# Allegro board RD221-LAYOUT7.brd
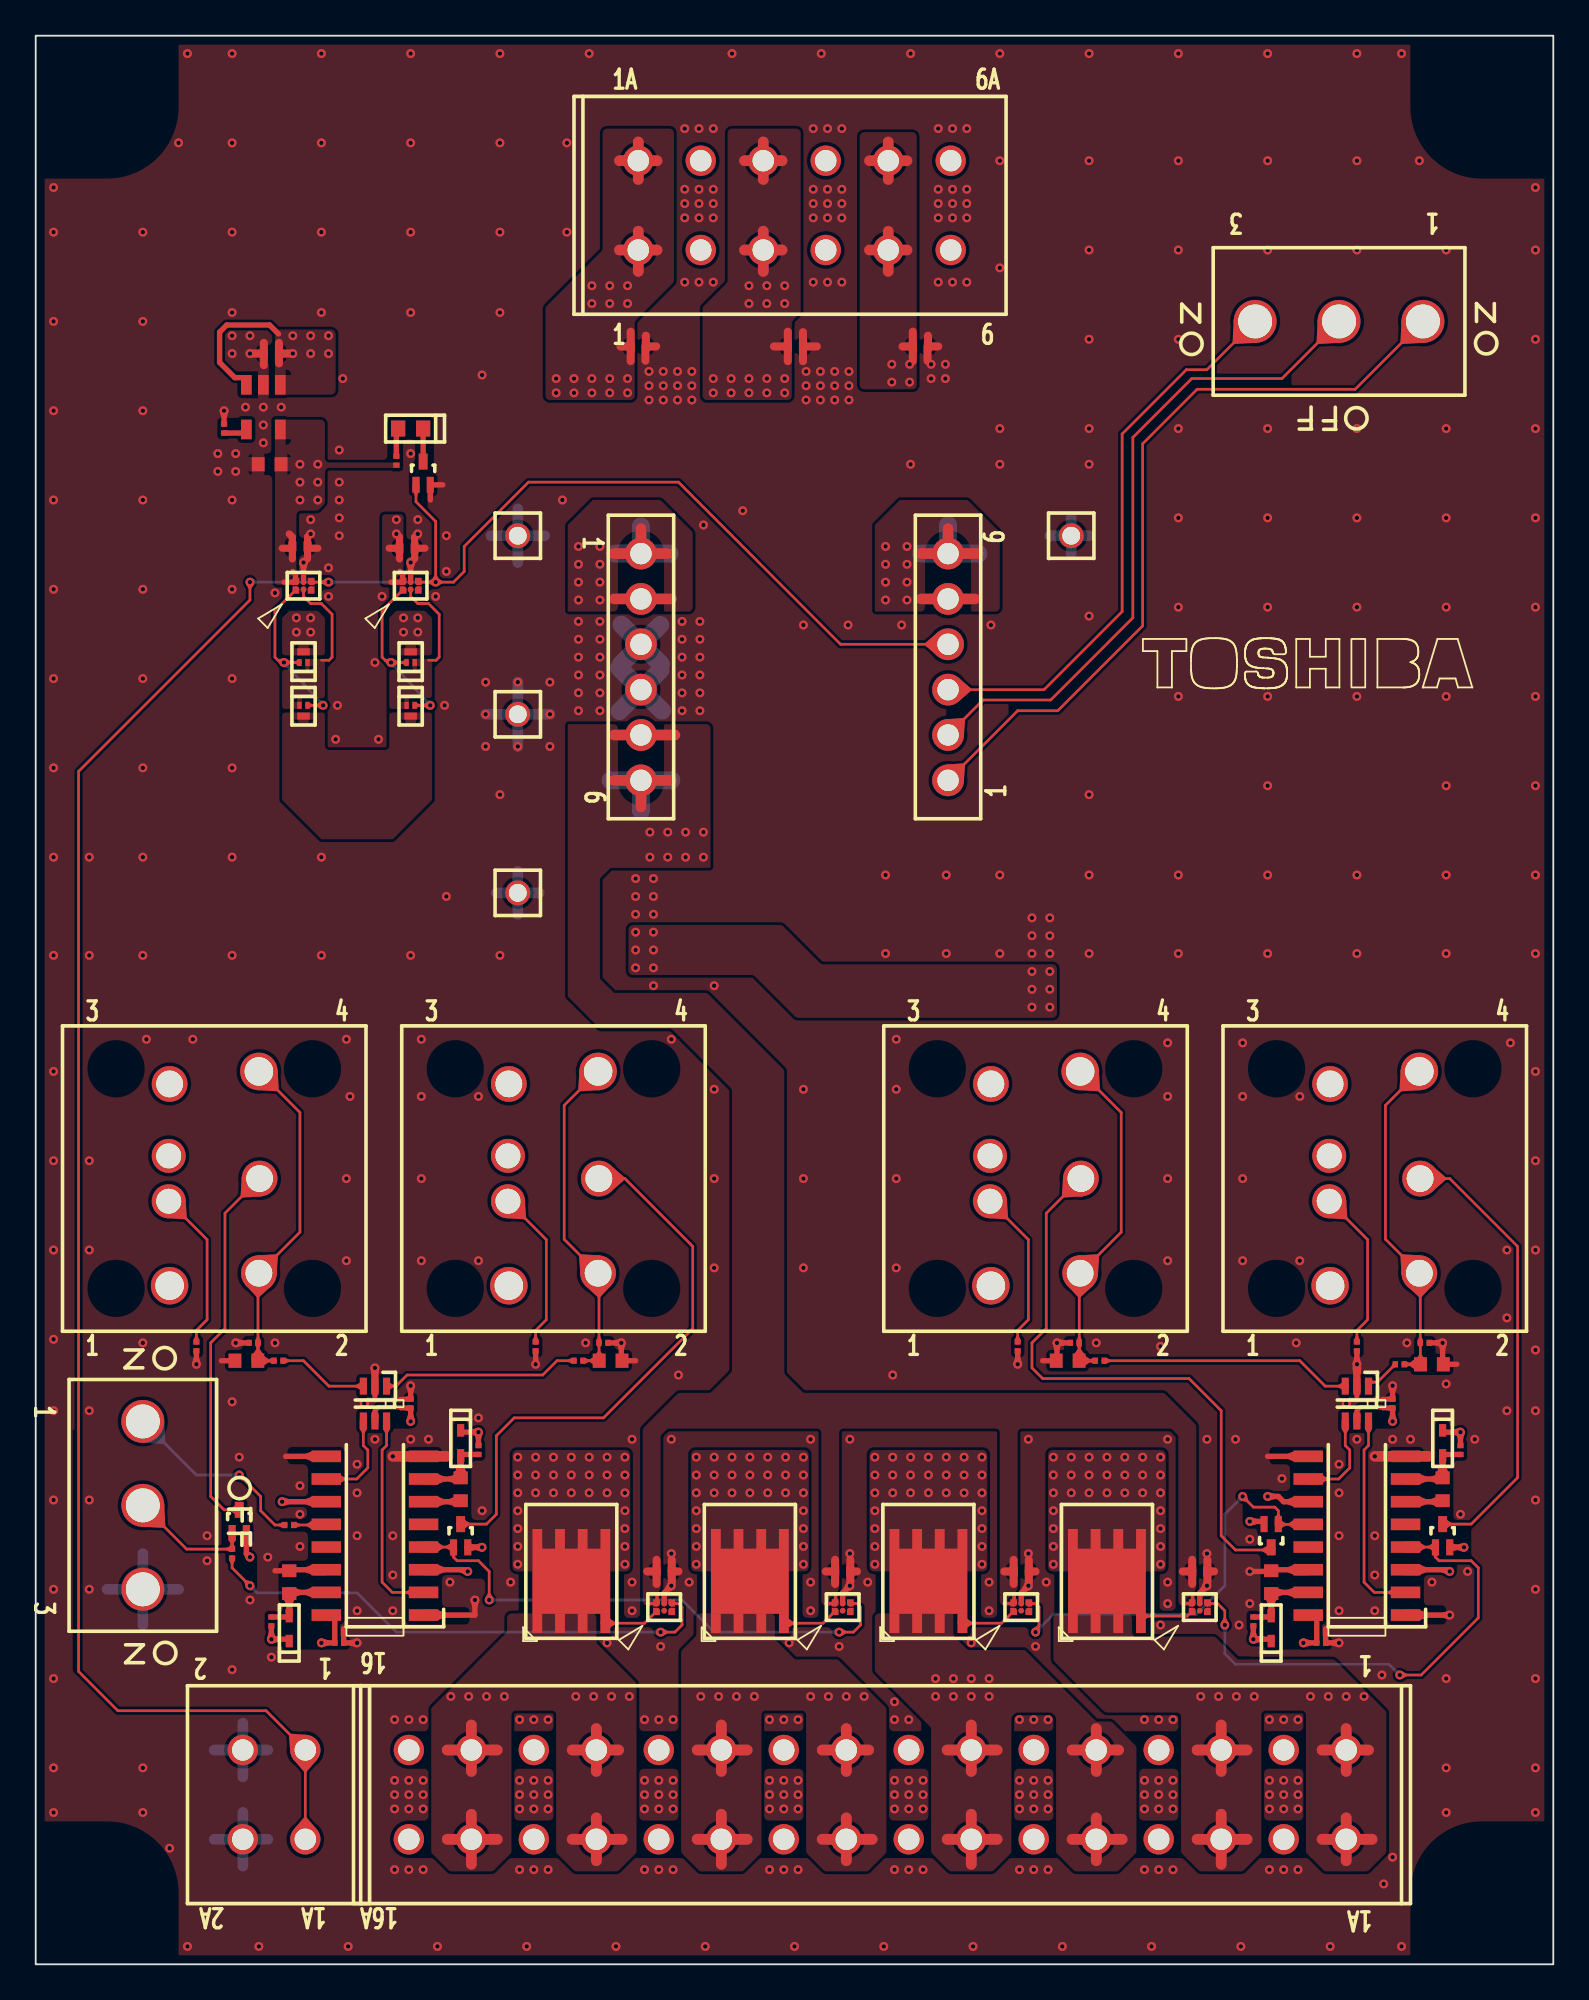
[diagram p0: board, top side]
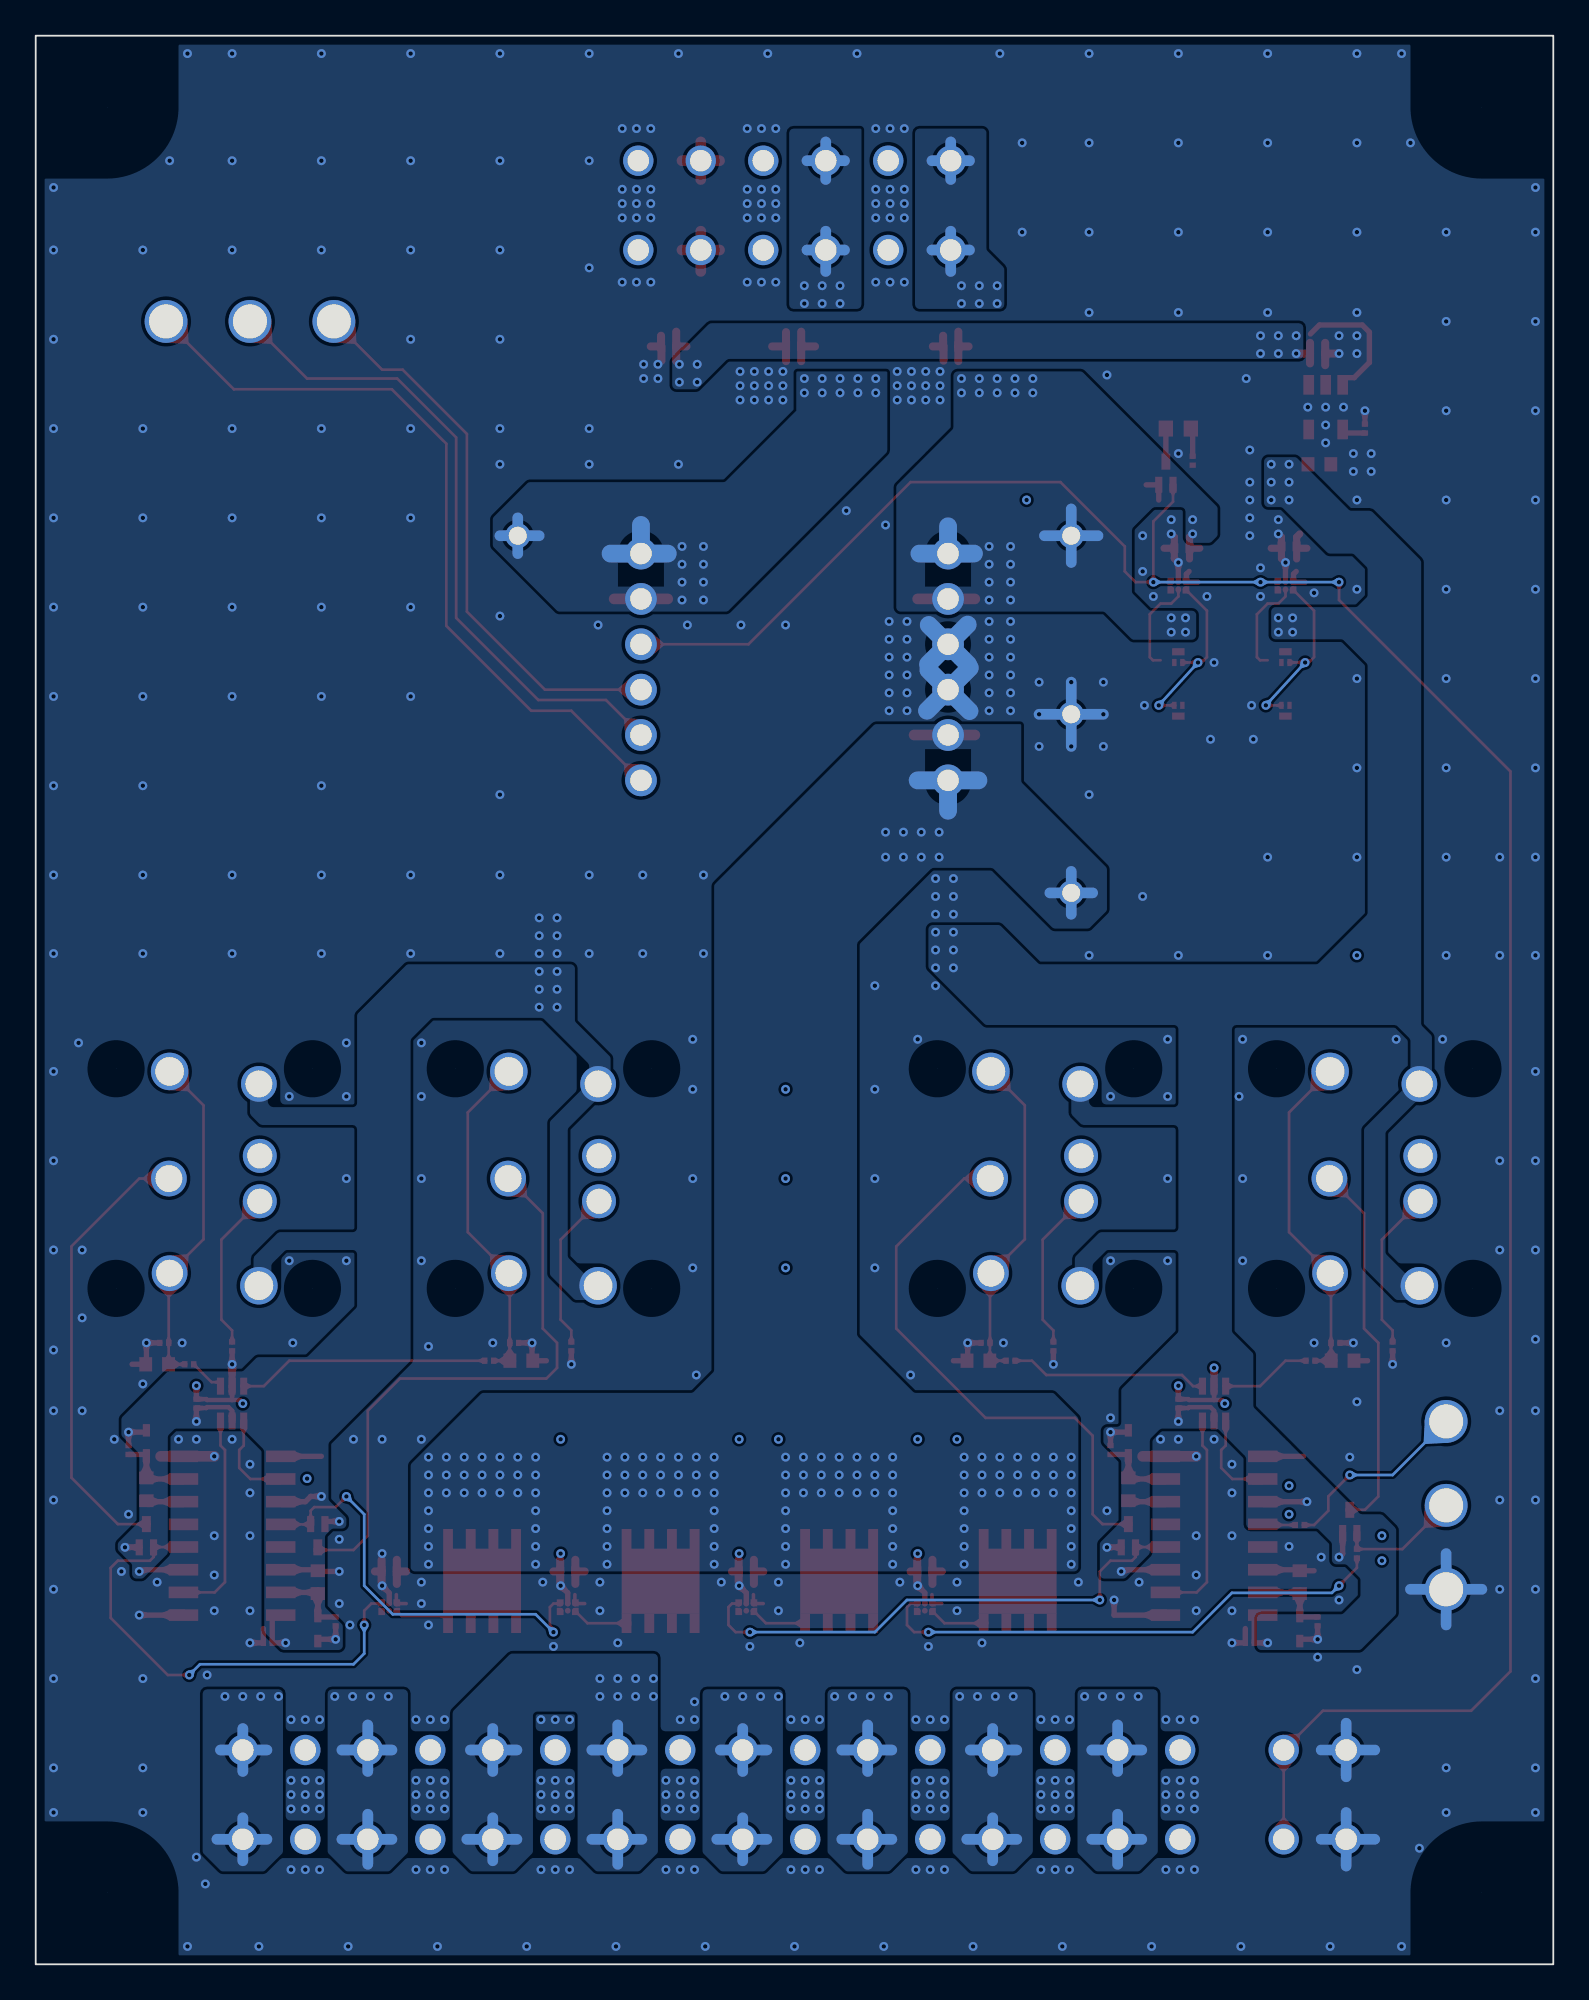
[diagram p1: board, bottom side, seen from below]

Outline 85 x 108 mm; copper layers: TOP, CONDUCTIVE2, CONDUCTIVE3, BOTTOM. Coordinates in mm from the lower left corner of the outline.
Outline path: rectangle 0,0 85,108

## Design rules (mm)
constraint set DEFAULT: 

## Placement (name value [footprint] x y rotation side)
C1  -  [KC00051KD]  20.8 79.3 0 top
C2  -  [KC00051KD]  14.8 79.4 0 top
C3  -  [KC00051KD]  65.2 22 0 top
C4  -  [KC00051KD]  55.2 22 0 top
C5  -  [KC00081KD]  78.2 33.6 0 top
C6  -  [KC00081KD]  57.8 33.8 180 top
C7  -  [KC00081KD]  78.8 26.6 90 top
C8  -  [KC00081KD]  69.2 21.4 270 top
C9  -  [KC00051KD]  45.2 22 0 top
C10  -  [KC00081KD]  32.2 33.8 0 top
C11  -  [KC00081KD]  11.8 33.8 180 top
C12  -  [KC00051KD]  35.2 22 0 top
C13  -  [KC00540KD]  72 18 180 top
C14  -  [KC00540KD]  17 18 180 top
C15  -  [KC00081KD]  14.2 21.4 270 top
C16  -  [KC00081KD]  23.8 26.6 270 top
C17  -  [KC00051KD]  13.2 90.2 180 top
C18  -  [KC00081KD]  13.1 84 180 top
C19  -  [KC00540KD]  10.55 86 270 top
C20  -  [KC00540KD]  76 31.4 270 top
C21  -  [KC00540KD]  21 31.4 270 top
C22  -  [KC00051KD]  49.55 90.6 0 top
C23  -  [KC00051KD]  42.55 90.6 0 top
C24  -  [KC00051KD]  33.75 90.6 0 top
CN1  -  [CU12010TD]  33.75 96 0 top
CN2  -  [CU12030TD]  73.4 12 180 top
CN3  -  [CU12020TD]  15.1 12 180 top
CN4  -  [CU11170TD]  51.1 66.3 90 top
CN5  -  [CU11170TD]  33.9 79 270 top
D1  -  [D8101D1KD]  78.8 29.2 90 top
D2  -  [D8101D1KD]  69.2 18.8 270 top
D3  -  [D8101D1KD]  23.8 29.2 90 top
D4  -  [D8101D1KD]  14.2 18.8 270 top
IC1  -  [MM00631KD]  12.75 87.2 180 top
IC2  -  [BA10620KD]  21 77.2 0 top
IC3  -  [BA10620KD]  15 77.2 0 top
IC4  -  [BA10620KD]  65.2 20 0 top
IC5  -  [SP10580KD]  74 24 90 top
IC6  -  [BA10620KD]  55.2 20 0 top
IC7  -  [BA10620KD]  45.2 20 0 top
IC8  -  [SP10580KD]  19 24 90 top
IC9  -  [BA10620KD]  35.2 20 0 top
IC10  -  [MM00451KD]  74 31.4 180 top
IC11  -  [MM00451KD]  19 31.4 180 top
LED1  -  [KC01110KD]  21 86 0 top
NOREF  -  [unnamed]  4 104 180 top
NOREF#2  -  [unnamed]  4 4 180 top
NOREF#3  -  [unnamed]  81 4 180 top
NOREF#4  -  [unnamed]  81 104 180 top
NOREF#5  -  [#2]  59.3 68.79 0 top
Q1  -  [LA10710KD]  21 73.2 90 top
Q2  -  [LA10710KD]  21 70.2 270 top
Q3  -  [LA10710KD]  15 73.2 90 top
Q4  -  [LA10710KD]  15 70.2 270 top
Q5  -  [MM11010KD]  21.7 83.5 0 top
Q6  -  [MM11010KD]  78.8 24 0 top
Q7  -  [SN10261KD]  60 22 0 top
Q8  -  [MM11010KD]  69.2 24 180 top
Q9  -  [SN10261KD]  50 22 0 top
Q10  -  [MM11010KD]  23.8 24 0 top
Q11  -  [SN10261KD]  40 22 0 top
Q12  -  [MM11010KD]  11.4 24.8 0 top
Q13  -  [SN10261KD]  30 22 0 top
R1  -  [KC00540KD]  74 34.6 270 top
R2  -  [KC00540KD]  55 34.6 270 top
R3  -  [KC00540KD]  58.2 34.8 180 top
R4  -  [KC00540KD]  77.8 34.8 0 top
R5  -  [KC00540KD]  20.2 84.2 270 top
R6  -  [KC00540KD]  79.8 28.8 270 top
R7  -  [KC00540KD]  68.2 19.2 90 top
R8  -  [KC00540KD]  28 34.6 270 top
R9  -  [KC00540KD]  31.8 34.8 0 top
R10  -  [KC00540KD]  12.2 34.8 180 top
R11  -  [KC00540KD]  24.8 28.8 270 top
R12  -  [KC00540KD]  13.2 19.2 90 top
R13  -  [KC00540KD]  9 34.6 270 top
R14  -  [KC00540KD]  76.4 33.6 0 top
R16  -  [KC00540KD]  30.4 33.8 0 top
R17  -  [KC00540KD]  13.6 33.8 0 top
R18  -  [KC00540KD]  14.2 24.6 0 top
R19  -  [KC00540KD]  11 23 270 top
R20  -  [KC00540KD]  59.6 33.8 0 top
SW1  -  [OD11430TD]  75 44 0 top
SW2  -  [OD11430TD]  56 44 0 top
SW3  -  [OD11430TD]  29 44 0 top
SW4  -  [OD11430TD]  10 44 0 top
SW5  -  [OD11420TD]  6 30.4 270 top
SW6  -  [OD11420TD]  77.7 92 180 top
TP1  -  [DP002X0KD]  27 80 0 top
TP2  -  [DP002X0KD]  58 80 0 top
TP3  -  [DP002X0KD]  27 60 0 top
TP4  -  [DP002X0KD]  27 70 0 top

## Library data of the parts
C1-C4 C9 C12 C17 C22-C24 = DP0000016125
C5 C6 C10 C11 = DP0000149011
C7 C8 C15 C16 = DP0000017116
C13 C14 C20 C21 = DP0000015406
C18 = DP0008993000
C19 = DP0000015127
CN1 = DP0010576000
CN2 = DP0010577000
CN3 = DP0010578000
CN4 CN5 = DP0010574000
D1-D4 = DP0005002000
IC1 = DP0010569000
IC2 = DP0010565000
IC3 IC4 IC6 IC7 IC9 = DP0010566000
IC5 IC8 = DP0010568000
IC10 IC11 = DP0010608000
LED1 = DP0010573000
Q1-Q4 = DP0010564000
Q5 = DP0010015000
Q6 Q8 Q10 Q12 = DP0010570000
Q7 Q9 Q11 Q13 = DP0010567000
R1 R2 R5 R8 R13 = DP0000152048
R3 R4 R9 R10 = DP0000152088
R6 R11 = DP0000152104
R7 R12 = DP0000155128
R14 R16-R20 = DP0000155000
SW1-SW4 = DP0010571000
SW5 SW6 = DP0010575000
TP1-TP4 = DP9000817000

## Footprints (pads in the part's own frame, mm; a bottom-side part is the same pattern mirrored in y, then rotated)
BA10620KD
  round 0.325 smd: A1(-0.4,-0.2) A2(-0.4,0.2) B1(0,-0.2) B2(0,0.2) C1(0.4,-0.2) C2(0.4,0.2)
CU11170TD
  round 1.778 hole 1.2: 1(0,0) 2(2.54,0) 3(5.08,0) 4(7.62,0) 5(10.16,0) 6(12.7,0)
CU12010TD
  round 1.7 hole 1.2: 1(0,0) 1A(0,5) 2(3.5,0) 2A(3.5,5) 3(7,0) 3A(7,5) 4(10.5,0) 4A(10.5,5) 5(14,0) 5A(14,5) 6(17.5,0) 6A(17.5,5)
CU12020TD
  round 1.7 hole 1.2: 1(0,0) 1A(0,5) 2(3.5,0) 2A(3.5,5)
CU12030TD
  round 1.7 hole 1.2: 1(0,0) 1A(0,5) 2(3.5,0) 2A(3.5,5) 3(7,0) 3A(7,5) 4(10.5,0) 4A(10.5,5) 5(14,0) 5A(14,5) 6(17.5,0) 6A(17.5,5) 7(21,0) 7A(21,5) 8(24.5,0) 8A(24.5,5) 9(28,0) 9A(28,5) 10(31.5,0) 10A(31.5,5) 11(35,0) 11A(35,5) 12(38.5,0) 12A(38.5,5) 13(42,0) 13A(42,5) 14(45.5,0) 14A(45.5,5) 15(49,0) 15A(49,5) 16(52.5,0) 16A(52.5,5)
D8101D1KD
  rect 0.7x0.4 smd: A(-0.7,0) C(0.7,0)
DP002X0KD
  round 1.397 hole 1: 1(0,0)
KC00051KD
  rect 0.45x0.55 smd: 1(-0.425,0) 2(0.425,0)
KC00081KD
  rect 0.72x0.8 smd: 1(-0.64,0) 2(0.64,0)
KC00540KD
  rect 0.3x0.35 smd: 1(-0.25,0) 2(0.25,0)
KC01110KD
  rect 0.8x0.9 smd: A(-0.7,0) C(0.7,0)
LA10710KD
  rect 0.4x0.7 smd: D(0.3,0)
  rect 0.4x0.25 smd: G(-0.3,0.225) S(-0.3,-0.225)
MM00451KD
  rect 0.4x0.95 smd: 1(-0.65,-0.975) 2(0,-0.975) 3(0.65,-0.975) 4(0.65,0.975) 5(0,0.975) 6(-0.65,0.975)
MM00631KD
  rect 0.6x1.1 smd: 1(-0.95,-1.25) 2(0,-1.25) 3(0.95,-1.25) 4(0.95,1.25) 5(-0.95,1.25)
MM11010KD
  rect 0.4x0.9 smd: B(-0.4,-0.65) E(0.4,-0.65)
  rect 0.5x0.9 smd: C(0,0.65)
OD11420TD
  round 2.4 hole 1.9: 1(0,0) 2(4.7,0) 3(9.4,0)
OD11430TD
  round 0.01 hole 2.2 unplated: (-5.5,6.15) (-5.5,-6.15) (5.5,6.15) (5.5,-6.15)
  round 2.1 hole 1.6: 1(-2.5,-6) 4(2.5,6)
  round 2 hole 1.5: 2(2.5,-5.3) 3(-2.5,5.3) LC(2.54,0)
  round 1.9 hole 1.4: L1(-2.55,1.27) L2(-2.55,-1.27)
SN10261KD
  rect 0.55x1.1 smd: 1(-1.905,-2.9) 2(-0.635,-2.9) 3(0.635,-2.9) 4(1.905,-2.9)
  custom 1.09x1.09 smd: 5(0,0)
SP10580KD
  rect 0.65x1.65 smd: 1(-4.445,-2.725) 2(-3.175,-2.725) 3(-1.905,-2.725) 4(-0.635,-2.725) 5(0.635,-2.725) 6(1.905,-2.725) 7(3.175,-2.725) 8(4.445,-2.725) 9(4.445,2.725) 10(3.175,2.725) 11(1.905,2.725) 12(0.635,2.725) 13(-0.635,2.725) 14(-1.905,2.725) 15(-3.175,2.725) 16(-4.445,2.725)
unnamed
  round 0.01 hole 3.5 unplated: (0,0)

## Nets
GND: C1.2 C2.2 C3.2 C4.2 C5.2 C6.2 C8.1 C9.2 C10.2 C11.2 C12.2 C13.1 C14.1 C15.1 C17.2 C18.2 C19.1 C20.1 C21.1 C22.2 C23.2 C24.2 CN1.2 CN1.2A CN1.4 CN1.4A CN1.6 CN1.6A CN2.2 CN2.2A CN2.4 CN2.4A CN2.6 CN2.6A CN2.8 CN2.8A CN2.10 CN2.10A CN2.12 CN2.12A CN2.14 CN2.14A CN2.16 CN2.16A CN3.2 CN3.2A CN5.3 CN5.4 IC1.2 IC2.B2 IC3.B2 IC4.B2 IC5.1 IC5.8 IC5.9 IC5.14 IC6.B2 IC7.B2 IC8.1 IC8.8 IC8.9 IC8.14 IC9.B2 IC10.2 IC11.2 Q5.E R1.2 R2.2 R3.2 R4.2 R8.2 R9.2 R10.2 R13.2 SW5.3 TP4.1
VDD: C17.1 C22.1 CN1.5 CN1.5A IC1.1 IC1.3
VINA: C1.1 C24.1 CN1.1 CN1.1A CN5.1 CN5.2 IC2.A2 Q1.D TP1.1
VINB: C23.1 CN1.3 CN1.3A CN4.5 CN4.6 TP2.1
FLAG: CN3.1 CN3.1A CN4.4 IC2.C2 IC3.C2 Q5.B
LOADA: CN2.1 CN2.1A CN2.3 CN2.3A Q7.1 Q7.2 Q7.3
LOADB: CN2.5 CN2.5A CN2.7 CN2.7A Q9.1 Q9.2 Q9.3
LOADC: CN2.9 CN2.9A CN2.11 CN2.11A Q11.1 Q11.2 Q11.3
LOADD: CN2.13 CN2.13A CN2.15 CN2.15A Q13.1 Q13.2 Q13.3
SIG15: LED1.A R5.1
SIG46: IC2.B1 Q1.S Q2.S
SIG166: IC2.A1 Q1.G Q2.G
SIG189: IC3.A1 Q3.G Q4.G
SIG190: IC3.B1 Q3.S Q4.S
SIG193: C19.2 IC1.4
SIG225: C7.1 IC5.6
SIG229: IC5.10 IC10.4
SIG230: C8.2 D2.A IC5.15 R7.2
SIG250: C7.2 D1.A IC5.7 R6.2
SIG275: C5.1 R4.1 R14.2 SW1.2 SW1.4
SIG309: R2.1 SW2.L2
SIG313: C6.1 R3.1 R20.1 SW2.2 SW2.4
SIG315: C10.1 R9.1 R16.2 SW3.2 SW3.4
SIG318: C16.1 D3.A IC8.7 R11.2
SIG321: C16.2 IC8.6
SIG324: IC8.10 IC11.4
SIG326: R13.1 SW4.L2
SIG328: R8.1 SW3.L2
SIG332: C15.2 D4.A IC8.15 R12.2
SIG333: C11.1 R10.1 R17.1 SW4.2 SW4.4
SIG335: IC8.12 R18.2
SIG338: IC7.A1 Q11.4
SIG339: IC6.A1 Q9.4
SIG340: IC4.A1 Q7.4
SIG341: IC9.A1 Q13.4
SIG345: IC10.3 R20.2
SIG347: IC9.C2 R19.2
SIG348: R18.1 SW5.1
SIG3334: LED1.C Q5.C
SIG3335: Q6.C SW1.LC
SIG3337: Q8.C SW2.LC
SIG3338: Q10.C SW3.LC
SIG3340: Q12.C SW4.LC
SIG3348: R1.1 SW1.L2
SIG3352: IC5.2 IC10.6
SIG3353: IC10.1 R14.1
SIG3354: IC8.2 IC11.6
SIG3355: IC11.1 R16.1
SIG3356: IC11.3 R17.2
SIG3359: CN4.3 SW6.3
SIG3360: CN4.2 SW6.2
SIG3361: CN4.1 SW6.1
SW_CONTA: IC4.C2 IC5.4 Q6.B
SW_CONTB: IC5.12 IC6.C2 Q8.B
SW_CONTC: IC7.C2 IC8.4 Q10.B
SW_CONTD: Q12.B R19.1 SW5.2
VOUT: C3.1 C4.1 C9.1 C12.1 CN5.5 CN5.6 IC4.A2 IC6.A2 IC7.A2 IC9.A2 Q7.5 Q9.5 Q11.5 Q13.5 TP3.1
VP_4R8: C2.1 C13.2 C14.2 C18.1 C20.2 C21.2 D1.C D2.C D3.C D4.C IC1.5 IC3.A2 IC5.3 IC5.11 IC5.16 IC8.3 IC8.11 IC8.16 IC10.5 IC11.5 Q3.D Q6.E Q8.E Q10.E Q12.E R5.2 R6.1 R7.1 R11.1 R12.1 SW1.1 SW1.3 SW2.1 SW2.3 SW3.1 SW3.3 SW4.1 SW4.3
VP_SW: Q2.D Q4.D

Pads without a net: IC2 C1; IC3 C1; IC4 B1 C1; IC5 5 13; IC6 B1 C1; IC7 B1 C1; IC8 5 13; IC9 B1 C1; SW1 L1; SW2 L1; SW3 L1; SW4 L1

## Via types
v1: diameter 0.5, hole 0.25, TOP to BOTTOM, 881 vias

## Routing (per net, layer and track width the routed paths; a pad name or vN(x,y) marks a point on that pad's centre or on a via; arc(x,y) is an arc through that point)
GND: length 259.1
  TOP w0.25: 20.87,31.65 20.45,31.65 20.4,31.6 19,31.6 ; 19,32.1 19,31.6 ; 19,31.6 18.6,31.6 v1(18.4,31.4) ; 74,31.6 73.6,31.6 v1(73.4,31.4) ; 74,31.6 75.4,31.6 75.45,31.65 75.87,31.65 ; 74,31.6 74,32.1
  TOP w0.3: 72.25,18.8 C13.1 v1(73,18) ; C15.1 13.4,22.04 ; R13.2 v1(9,33.6) ; IC7.B2 45.2,20.8 v1(45.6,21.2) ; R2.2 v1(55,33.6) ; 78.8,33.64 v1(78.8,34.8) R4.2 ; 75.87,31.65 C20.1 v1(76,32.4) ; 20.87,31.65 C21.1 v1(21,32.4) ; C6.2 56.4,33.8 ; C11.2 10.4,33.8 ; IC6.B2 55.2,20.8 v1(55.6,21.2) ; R3.2 v1(57.2,34.8) 57.2,33.8 ; R8.2 v1(28,33.6) ; v1(18,18) C14.1 17.25,18.8 ; R1.2 v1(74,33.6) ; R10.2 v1(11.2,34.8) ; 15.58,22.09 14.26,22.09 ; 32.8,33.84 v1(32.8,34.8) R9.2 ; IC3.B2 v1(15,78.5) ; v1(24.6,20.4) 24.6,19.55 22.42,19.55 ; IC9.B2 35.2,20.8 v1(35.6,21.2) ; C5.2 79.6,33.6 ; 22.8,82.85 Q5.E 22.1,82 ; IC2.B2 v1(21,78.5) ; v1(65.6,21.2) 65.2,20.8 IC4.B2 ; 70.58,28.45 69,28.45 ; 77.42,19.55 v1(79.2,19.55) ; 70.58,22.09 69.25,22.09 ; C19.1 v1(10.55,87) ; v1(68,22) 69.16,22 ; C10.2 33.6,33.8 ; 15.58,28.45 14,28.45
  TOP w0.4: 74,32.1 IC10.2 74,33.4 ; v1(15,78.5) 15.22,78.72 15.22,79.3 ; v1(19,33.4) IC11.2 19,32.1 ; v1(21.4,80.1) 21.23,79.92 C1.2 ; C1.2 21.8,79.3 ; C1.2 21.23,78.72 v1(21,78.5) ; 15.22,79.3 15.8,79.3 ; 15.22,79.3 15.22,79.92 v1(15.4,80.1)
  TOP w0.45: C3.2 65.62,21.4 ; C3.2 66,22 ; C3.2 65.62,22.65 ; C12.2 36,22 ; C12.2 35.62,22.65 ; C12.2 35.62,21.4 ; 12.78,90.2 12.78,90.8 ; 12.78,90.2 v1(12,90.2) ; 12.78,90.2 12.78,89.55 ; 34.15,90.6 34.15,89.8 ; C9.2 45.62,22.65 ; C9.2 46,22 ; C9.2 45.62,21.4 ; 49.95,90.6 49.95,89.8 ; 34.17,91.2 C24.2 34.75,90.6 ; 49.98,91.2 49.98,90.6 50.55,90.6 ; C4.2 55.62,22.65 ; C4.2 55.62,21.4 ; C4.2 56,22 ; 42.98,90.6 42.98,91.4 ; 42.98,90.6 42.98,89.78 ; 42.98,90.6 43.75,90.6
  TOP w0.6: IC5.9 70.58,28.45 ; 23,28.45 IC8.8 v1(20,28.45) ; v1(75,28.45) IC5.8 78,28.45 ; IC8.1 22.42,19.55 ; IC5.14 70.58,22.09 ; IC5.1 77.42,19.55 ; IC8.9 15.58,28.45 ; IC8.14 15.58,22.09
  CONDUCTIVE2 w1: CN2.8A v1(48.9,5.3) ; CN2.8A 47.25,7 ; CN2.8A 50.45,7 ; CN2.8A v1(48.9,8.7) ; CN2.14 26.45,12 ; CN2.14 v1(27.9,10.3) ; CN2.14 v1(27.9,13.7) ; CN2.14 29.45,12 ; CN2.16 19.45,12 ; CN2.16 v1(20.9,13.7) ; CN2.16 v1(20.9,10.3) ; CN2.16 22.45,12 ; CN2.6A 57.45,7 ; CN2.6A v1(55.9,5.3) ; CN2.6A 54.25,7 ; CN2.6A v1(55.9,8.7) ; CN2.12 v1(34.9,10.3) ; CN2.12 36.45,12 ; CN2.12 33.45,12 ; CN2.12 v1(34.9,13.7) ; CN2.2 71.45,12 ; CN2.2 v1(69.9,13.7) ; CN2.2 68.45,12 ; CN2.2 v1(69.9,10.3) ; CN1.6 52.75,96 ; CN1.6 51.25,94.3 ; CN1.6 49.75,96 ; CN1.6 51.25,97.7 ; CN2.10A 40.25,7 ; CN2.10A v1(41.9,8.7) ; CN2.10A 43.45,7 ; CN2.10A v1(41.9,5.3) ; CN2.16A v1(20.9,8.7) ; CN2.16A 22.45,7 ; CN2.16A v1(20.9,5.3) ; CN2.16A 19.25,7 ; CN2.6 v1(55.9,10.3) ; CN2.6 54.45,12 ; CN2.6 57.45,12 ; CN2.6 v1(55.9,13.7) ; CN1.6A 49.75,101 ; CN1.6A 52.75,101 ; CN1.6A 51.25,102.7 ; CN1.6A 51.25,99.5 ; CN1.2A 37.25,99.5 ; CN1.2A 37.25,102.7 ; CN1.2A 35.75,101 ; CN1.2A 38.75,101 ; CN2.4 61.45,12 ; CN2.4 v1(62.9,10.3) ; CN2.4 64.45,12 ; CN2.4 v1(62.9,13.7) ; CN1.4 45.75,96 ; CN1.4 44.25,94.3 ; CN1.4 44.25,97.7 ; CN1.4 42.75,96 ; CN2.8 47.45,12 ; CN2.8 v1(48.9,10.3) ; CN2.8 v1(48.9,13.7) ; CN2.8 50.45,12 ; CN1.2 35.75,96 ; CN1.2 37.25,94.3 ; CN1.2 38.75,96 ; CN1.2 37.25,97.7 ; CN2.10 v1(41.9,10.3) ; CN2.10 v1(41.9,13.7) ; CN2.10 40.45,12 ; CN2.10 43.45,12 ; CN2.2A 68.25,7 ; CN2.2A 71.45,7 ; CN2.2A v1(69.9,8.7) ; CN2.2A v1(69.9,5.3) ; CN2.14A v1(27.9,8.7) ; CN2.14A 29.45,7 ; CN2.14A 26.25,7 ; CN2.14A v1(27.9,5.3) ; CN2.12A v1(34.9,5.3) ; CN2.12A 33.25,7 ; CN2.12A 36.45,7 ; CN2.12A v1(34.9,8.7) ; CN1.4A 42.75,101 ; CN1.4A 44.25,99.5 ; CN1.4A 44.25,102.7 ; CN1.4A 45.75,101 ; CN2.4A v1(62.9,8.7) ; CN2.4A v1(62.9,5.3) ; CN2.4A 61.25,7 ; CN2.4A 64.45,7
  BOTTOM w0.6: CN3.2A 13,7 ; CN3.2A 11.6,5.5 ; CN3.2A 10,7 ; CN3.2A 11.6,8.5 ; CN3.2 10,12 ; CN3.2 11.6,13.5 ; CN3.2 11.6,10.5 ; CN3.2 13,12 ; SW5.3 4,21 ; SW5.3 6,23 ; SW5.3 6,19 ; SW5.3 8,21 ; TP4.1 v1(28.8,70) ; TP4.1 v1(27,71.8) ; TP4.1 v1(27,68.2) ; TP4.1 v1(25.2,70)
  BOTTOM w1: CN5.4 32.7,70.18 ; CN5.4 35,72.48 ; CN5.4 35.08,70.2 ; CN5.4 32.68,72.6 ; CN5.3 32.8,75.02 ; CN5.3 34.98,75 ; CN5.3 32.78,72.8 ; CN5.3 35.02,72.8
  vias: v1(1,99.5) v1(1,97) v1(1,92) v1(1,87) v1(1,82) v1(1,77) v1(1,72) v1(1,67) v1(1,62) v1(1,56.5) v1(1,50) v1(1,45) v1(1,40) v1(1,35) v1(1,31) v1(1,26) v1(1,21) v1(1,16) v1(1,11) v1(1,8.5) v1(3,62) v1(3,56.5) v1(3,45) v1(3,40) v1(3,31) v1(3,26) v1(3,21) v1(6,97) v1(6,92) v1(6,87) v1(6,82) v1(6,77) v1(6,72) v1(6,67) v1(6,62) v1(6,56.5) v1(6,34.8) v1(6,11) v1(6,8.5) v1(6.2,51.8) v1(7.5,6.5) v1(8,102) v1(8.5,107) v1(8.5,1) v1(8.8,51.8) v1(9.6,24) v1(9.6,22.6) v1(10.2,84.6) v1(10.2,83.6) v1(11,107) v1(11,102) v1(11,97) v1(11,92.5) v1(11,91.2) v1(11,90.2) v1(11,82) v1(11,77) v1(11,72) v1(11,67) v1(11,62) v1(11,56.5) v1(11,31.5) v1(11,16.5) v1(11.2,84.6) v1(11.2,83.6) v1(11.4,28.4) v1(11.75,87.2) v1(12,91.2) v1(12,20.4) v1(12.5,1) v1(12.75,87.2) v1(12.75,86.2) v1(12.75,85.2) v1(13,22.8) v1(13.2,17.2) v1(13.4,76.8) v1(13.4,34.8) v1(13.75,87.2) v1(14.8,26.8) v1(14.8,25.2) v1(14.8,23.4) v1(15.4,80.9) v1(16,107) v1(16,102) v1(16,97) v1(16,92.5) v1(16,62) v1(16,56.5) v1(16.4,78.2) v1(16.4,76.6) v1(16.8,68.6) v1(16.9,70.5) v1(17,84.8) v1(17,83) v1(17,82) v1(17,81) v1(17,80) v1(17.2,88.8) v1(17.4,51.8) v1(17.4,44) v1(17.4,39.4) v1(17.5,1) v1(17.6,48.6) v1(18,28) v1(18,26.4) v1(18,24) v1(18,19.8) v1(19,72.9) v1(19,29.4) v1(19.2,68.6) v1(19.4,76.6) v1(20,24) v1(20,21.8) v1(20,19.8) v1(20.1,13.7) v1(20.1,10.3) v1(20.1,9.5) v1(20.1,8.7) v1(20.1,5.3) v1(20.9,9.5) v1(21,107) v1(21,102) v1(21,97) v1(21,92.5) v1(21,84.6) v1(21,56.5) v1(21,29.4) v1(21.4,80.9) v1(21.6,51.8) v1(21.6,48.6) v1(21.6,44) v1(21.6,39.4) v1(21.7,13.7) v1(21.7,10.3) v1(21.7,9.5) v1(21.7,8.7) v1(21.7,5.3) v1(22,29.4) v1(22.4,76.6) v1(22.5,1) v1(22.9,70.5) v1(23,80) v1(23,78) v1(23,59.8) v1(23.2,21.4) v1(24.8,48.6) v1(24.8,39.4) v1(24.8,30.6) v1(25,89) v1(25,25.4) v1(25.2,71.8) v1(25.2,68.2) v1(26,107) v1(26,102) v1(26,97) v1(26,92.5) v1(26,65.5) v1(26,56.5) v1(26.6,21.4) v1(27.1,13.7) v1(27.1,10.3) v1(27.1,9.5) v1(27.1,8.7) v1(27.1,5.3) v1(27.5,1) v1(27.9,9.5) v1(28.7,13.7) v1(28.7,10.3) v1(28.7,9.5) v1(28.7,8.7) v1(28.7,5.3) v1(28.8,71.8) v1(28.8,68.2) v1(29.5,82) v1(29.75,102) v1(29.75,97) v1(30.4,75.2) v1(30.4,74.2) v1(30.4,73.2) v1(30.4,72.2) v1(30.4,71.2) v1(30.4,70.2) v1(30.8,34.8) v1(31,107) v1(31.6,75.2) v1(31.6,74.2) v1(31.6,73.2) v1(31.6,72.2) v1(31.6,71.2) v1(31.6,70.2) v1(32,18) v1(32.5,1) v1(33.4,29.4) v1(33.4,21.4) v1(33.4,19.8) v1(33.6,60.8) v1(33.6,59.8) v1(33.6,58.8) v1(34.1,13.7) v1(34.1,10.3) v1(34.1,9.5) v1(34.1,8.7) v1(34.1,5.3) v1(34.35,89.2) v1(34.35,88.4) v1(34.35,87.6) v1(34.6,60.8) v1(34.6,59.8) v1(34.6,58.8) v1(34.6,54.8) v1(34.9,9.5) v1(35,17.8) v1(35.15,89.2) v1(35.15,88.4) v1(35.15,87.6) v1(35.6,51.8) v1(35.6,29.4) v1(35.6,23) v1(35.7,13.7) v1(35.7,10.3) v1(35.7,9.5) v1(35.7,8.7) v1(35.7,5.3) v1(35.95,89.2) v1(35.95,88.4) v1(35.95,87.6) v1(36,33) v1(36.2,75.2) v1(36.2,74.2) v1(36.2,73.2) v1(36.2,72.2) v1(36.2,71.2) v1(36.2,70.2) v1(36.35,102.8) v1(36.35,99.4) v1(36.35,98.6) v1(36.35,97.8) v1(36.35,94.2) v1(36.6,21.4) v1(36.75,89.2) v1(36.75,88.4) v1(36.75,87.6) v1(37.15,102.8) v1(37.15,99.4) v1(37.15,98.6) v1(37.15,97.8) v1(37.15,94.2) v1(37.2,75.2) v1(37.2,74.2) v1(37.2,73.2) v1(37.2,72.2) v1(37.2,71.2) v1(37.2,70.2) v1(37.4,80.6) v1(37.5,1) v1(37.95,102.8) v1(37.95,99.4) v1(37.95,98.6) v1(37.95,97.8) v1(37.95,94.2) v1(38,54.8) v1(38,49) v1(38,44) v1(38,39) v1(39,107) v1(39.6,81.4) v1(41.1,13.7) v1(41.1,10.3) v1(41.1,9.5) v1(41.1,8.7) v1(41.1,5.3) v1(41.9,9.5) v1(42.2,18) v1(42.5,1) v1(42.7,13.7) v1(42.7,10.3) v1(42.7,9.5) v1(42.7,8.7) v1(42.7,5.3) v1(43,75) v1(43,49) v1(43,44) v1(43,39) v1(43.15,89.2) v1(43.15,88.4) v1(43.15,87.6) v1(43.4,29.4) v1(43.4,21.4) v1(43.4,19.8) v1(43.55,102.8) v1(43.55,99.4) v1(43.55,98.6) v1(43.55,97.8) v1(43.55,94.2) v1(44,107) v1(43.95,89.2) v1(43.95,88.4) v1(43.95,87.6) v1(44.35,102.8) v1(44.35,99.4) v1(44.35,98.6) v1(44.35,97.8) v1(44.35,94.2) v1(44.75,89.2) v1(44.75,88.4) v1(44.75,87.6) v1(45,17.8) v1(45.15,102.8) v1(45.15,99.4) v1(45.15,98.6) v1(45.15,97.8) v1(45.15,94.2) v1(45.55,89.2) v1(45.55,88.4) v1(45.55,87.6) v1(45.5,75) v1(45.6,29.4) v1(45.6,23) v1(46.6,21.4) v1(47.5,1) v1(47.6,61) v1(47.6,56.6) v1(48,33) v1(48.1,14.7) v1(48.1,13.7) v1(48.1,10.3) v1(48.1,9.5) v1(48.1,8.7) v1(48.1,5.3) v1(48.2,51.8) v1(48.2,49) v1(48.2,44) v1(48.2,39) v1(48.5,75) v1(48.9,9.5) v1(49,107) v1(49,84) v1(49.7,10.3) v1(49.7,9.5) v1(49.7,8.7) v1(49.7,5.3) v1(50.15,89.6) v1(50.15,88.8) v1(50.55,102.8) v1(50.55,99.4) v1(50.55,98.6) v1(50.55,97.8) v1(50.55,94.2) v1(50.95,89.6) v1(50.95,88.8) v1(51,61) v1(51,56.6) v1(51.35,102.8) v1(51.35,99.4) v1(51.35,98.6) v1(51.35,97.8) v1(51.35,94.2) v1(52.15,102.8) v1(52.15,99.4) v1(52.15,98.6) v1(52.15,97.8) v1(52.15,94.2) v1(52.4,18) v1(52.5,1) v1(53.4,21.4) v1(53.4,19.8) v1(53.5,75) v1(54,107) v1(54,101) v1(54,95) v1(54,86) v1(54,84) v1(54,61) v1(54,56.6) v1(55.1,13.7) v1(55.1,10.3) v1(55.1,9.5) v1(55.1,8.7) v1(55.1,5.3) v1(55.6,29.4) v1(55.6,23) v1(55.8,58.6) v1(55.8,57.6) v1(55.8,56.6) v1(55.9,9.5) v1(56,17.8) v1(56.6,21.4) v1(56.7,13.7) v1(56.7,10.3) v1(56.7,9.5) v1(56.7,8.7) v1(56.7,5.3) v1(56.8,58.6) v1(56.8,57.6) v1(56.8,56.6) v1(57.5,1) v1(59,107) v1(59,101) v1(59,96) v1(59,91) v1(59,86) v1(59,84) v1(59,75.5) v1(59,65.5) v1(59,61) v1(59,56.6) v1(59.4,34.8) v1(62.1,13.7) v1(62.1,10.3) v1(62.1,9.5) v1(62.1,8.7) v1(62.1,5.3) v1(62.5,1) v1(62.9,9.5) v1(63,34.6) v1(63,19) v1(63.4,51.6) v1(63.4,48.6) v1(63.4,44) v1(63.4,39.4) v1(63.4,29.4) v1(63.4,21.4) v1(63.4,20.2) v1(63.7,13.7) v1(63.7,10.3) v1(63.7,9.5) v1(63.7,8.7) v1(63.7,5.3) v1(64,107) v1(64,101) v1(64,96) v1(64,91) v1(64,86) v1(64,81) v1(64,76) v1(64,71) v1(64,61) v1(64,56.6) v1(65.6,29.4) v1(65.6,23) v1(67.2,29.4) v1(67.4,19) v1(67.5,1) v1(67.6,51.6) v1(67.6,48.6) v1(67.6,44) v1(67.6,39.4) v1(68,23.8) v1(68,20.2) v1(69,107) v1(69,101) v1(69,96) v1(69,86) v1(69,81) v1(69,76) v1(69,71) v1(69,66) v1(69,61) v1(69,56.6) v1(69.1,13.7) v1(69.1,10.3) v1(69.1,9.5) v1(69.1,8.7) v1(69.1,5.3) v1(69.8,27.2) v1(69.9,9.5) v1(70.6,34.8) v1(70.7,13.7) v1(70.7,10.3) v1(70.7,9.5) v1(70.7,8.7) v1(70.7,5.3) v1(70.8,48.6) v1(70.8,39.4) v1(72.5,1) v1(73,28) v1(73,26.4) v1(73,24) v1(73,19.8) v1(74,107) v1(74,101) v1(74,96) v1(74,86) v1(74,81) v1(74,76) v1(74,71) v1(74,61) v1(74,56.6) v1(74,29.4) v1(75,24) v1(75,21.8) v1(75,19.8) v1(75.4,16.2) v1(75.5,4.5) v1(76,29.4) v1(76,6) v1(76.5,107) v1(76.5,1) v1(76.8,34.8) v1(77,29.4) v1(77.5,101) v1(78.2,21.4) v1(79,96) v1(79,86) v1(79,81) v1(79,76) v1(79,71) v1(79,66) v1(79,61) v1(79,56.6) v1(79,32.5) v1(79,16) v1(79,11) v1(79,8.5) v1(79.8,25.2) v1(80.2,22) v1(80.6,29.4) v1(82.4,40) v1(82.4,36.2) v1(82.4,31) v1(82.6,51.6) v1(84,99.5) v1(84,96) v1(84,91) v1(84,86) v1(84,81) v1(84,76) v1(84,71) v1(84,66) v1(84,61) v1(84,56.6) v1(84,50) v1(84,45) v1(84,40) v1(84,34.4) v1(84,31) v1(84,26) v1(84,21) v1(84,16) v1(84,11) v1(84,8.5)
VDD: length 19.9
  TOP w0.3: 13.6,91.3 13.1,91.8 10.7,91.8 10.3,91.4 10.3,89.7 11.15,88.85 11.78,88.85
  TOP w0.45: C22.1 48.55,90.6 ; C22.1 49.12,89.78 ; C22.1 49.12,91.42 ; C17.1 13.62,89.65 ; C17.1 13.62,90.8 ; C17.1 v1(14.4,90.2)
  TOP w0.6: 48.8,96 CN1.5 ; CN1.5 46.7,96 ; CN1.5 47.75,94.8 ; CN1.5 47.75,97.05 ; CN1.5A 47.75,102.05 ; CN1.5A 47.75,99.95 ; CN1.5A 48.8,101 ; CN1.5A 46.7,101
  vias: v1(14.4,91.2) v1(15.4,91.2) v1(15.4,90.2) v1(16.4,91.2) v1(16.4,90.2) v1(47.95,89.6) v1(47.95,88.6) v1(48.95,89.6) v1(48.95,88.6)
VINA: length 40.9
  TOP w0.3: 19.9,77.4 IC2.A2 20.55,77.45 20.55,77.85 20.4,78
  TOP w0.4: C1.1 19.8,79.3 ; C1.1 20.38,78.7 ; C1.1 20.38,79.92 v1(20.2,80.1)
  TOP w0.45: 33.33,91.42 C24.1 ; C24.1 33.33,89.78 ; C24.1 32.75,90.6
  TOP w0.6: CN1.1A 33.75,102.05 ; CN1.1A 34.8,101 ; CN1.1A 33.75,99.95 ; CN1.1A 32.7,101 ; CN5.1 32.4,79 ; CN5.1 33.9,80.4 ; CN5.1 35.4,79 ; 32.4,76.46 CN5.2 35.6,76.46 ; CN1.1 33.75,94.8 ; CN1.1 32.7,96 ; CN1.1 34.8,96 ; CN1.1 33.75,97.05
  BOTTOM w0.6: TP1.1 25.5,80 ; TP1.1 27,78.5 ; TP1.1 27,81.5 ; TP1.1 28.5,80 ; CN1.1 33.75,94.8 ; CN1.1 32.7,96 ; CN1.1 34.8,96 ; CN1.1 33.75,97.05 ; CN1.1A 33.75,99.95 ; CN1.1A 34.8,101 ; CN1.1A 33.75,102.05 ; CN1.1A 32.7,101
  BOTTOM w1: CN5.1 33.9,80.53 ; CN5.1 32.45,79 ; CN5.1 35.5,79
  vias: v1(20.2,80.9) v1(20.6,75.4) v1(20.6,74.6) v1(21.4,75.4) v1(21.4,74.6) v1(29.15,88.8) v1(29.15,88) v1(30.15,88.8) v1(30.15,88) v1(30.4,79.4) v1(30.4,78.4) v1(30.4,77.4) v1(30.4,76.4) v1(31.15,94) v1(31.15,93) v1(31.15,88.8) v1(31.15,88) v1(31.6,79.4) v1(31.6,78.4) v1(31.6,77.4) v1(31.6,76.4) v1(32.15,94) v1(32.15,93) v1(32.15,88.8) v1(32.15,88) v1(33.15,94) v1(33.15,93) v1(33.15,88.8) v1(33.15,88)
VINB: length 36.1
  TOP w0.45: C23.1 42.12,89.78 ; C23.1 42.12,91.42 ; C23.1 41.35,90.6
  TOP w0.6: CN1.3 40.75,97.05 ; CN1.3 41.8,96 ; CN1.3 39.7,96 ; CN1.3 40.75,94.8 ; 52.6,76.46 CN4.5 49.6,76.46 ; CN1.3A 40.75,102.05 ; CN1.3A 41.8,101 ; CN1.3A 40.75,99.95 ; CN1.3A 39.7,101 ; CN4.6 52.8,79 ; CN4.6 51.1,80.4 ; CN4.6 49.6,79
  BOTTOM w0.6: 41.8,96 CN1.3 ; CN1.3 40.75,97.05 ; CN1.3 39.7,96 ; CN1.3 40.75,94.8 ; 39.7,101 CN1.3A ; CN1.3A 40.75,102.05 ; CN1.3A 40.75,99.95 ; CN1.3A 41.8,101 ; TP2.1 59,80 ; TP2.1 58,79 ; TP2.1 56.8,80 ; TP2.1 58,81
  BOTTOM w1: CN4.6 52.8,79 ; CN4.6 49.6,79 ; CN4.6 51.1,80.6
  vias: v1(37.95,88.8) v1(37.95,88) v1(38.95,88.8) v1(38.95,88) v1(39.95,94) v1(39.95,93) v1(39.95,88.8) v1(39.95,88) v1(40.95,94) v1(40.95,93) v1(40.95,88.8) v1(40.95,88) v1(41.95,94) v1(41.95,93) v1(41.95,88.8) v1(41.95,88) v1(47.6,79.4) v1(47.6,78.4) v1(47.6,77.4) v1(47.6,76.4) v1(48.8,79.4) v1(48.8,78.4) v1(48.8,77.4) v1(48.8,76.4)
FLAG: length 138.4
  TOP w0.15: v1(22.4,77.4) 23.4,77.4 24,78 24,79.4 27.6,83 36,83 45.08,73.92 CN4.4 ; v1(22.4,77.4) IC2.C2 ; v1(22.4,77.4) 22.4,80.8 21.3,81.9 21.3,82.58 ; v1(12,77.4) 12,76.4 2.4,66.8 2.4,16.4 4.6,14.2 12.9,14.2 CN3.1 CN3.1A ; IC3.C2 v1(16.4,77.4)
  TOP w0.4: Q5.B 21.3,82.58
  BOTTOM w0.15: v1(22.4,77.4) v1(16.4,77.4) v1(12,77.4)
LOADA: length 42.4
  TOP w0.6: CN2.1A 73.4,8.2 ; CN2.1A 73.4,5.8 ; CN2.1A 72.05,7 ; CN2.1A 74.85,7 ; CN2.3A 65.05,7 ; CN2.3A 66.4,8.4 ; CN2.3A 67.85,7 ; CN2.3A 66.4,5.6 ; CN2.1 72.05,12 ; CN2.1 73.4,10.8 ; CN2.1 74.65,12 ; CN2.1 73.4,13.2 ; CN2.3 65.05,12 ; CN2.3 66.4,13.4 ; CN2.3 67.85,12 ; CN2.3 66.4,10.8
  BOTTOM w0.6: CN2.1A 74.85,7 ; CN2.1A 73.4,8.2 ; CN2.1A 72.05,7 ; CN2.1A 73.4,5.8 ; CN2.3 67.85,12 ; CN2.3 66.4,10.8 ; CN2.3 65.05,12 ; CN2.3 66.4,13.4 ; CN2.1 73.4,10.8 ; CN2.1 73.4,13.2 ; CN2.1 72.05,12 ; CN2.1 74.65,12 ; CN2.3A 65.05,7 ; CN2.3A 66.4,5.6 ; CN2.3A 66.4,8.4 ; CN2.3A 67.85,7
  vias: v1(65.25,15) v1(66.25,15) v1(67.25,15) v1(68.25,15) v1(71.4,15) v1(72.4,15) v1(73.4,15) v1(74.4,15)
LOADB: length 42.4
  TOP w0.6: CN2.7A 53.85,7 ; CN2.7A 52.4,8.4 ; CN2.7A 52.4,5.6 ; CN2.7A 51.05,7 ; CN2.5 59.4,13.2 ; CN2.5 59.4,10.8 ; CN2.5 58.05,12 ; CN2.5 60.65,12 ; CN2.7 52.4,10.8 ; CN2.7 53.85,12 ; CN2.7 52.4,13.4 ; CN2.7 51.05,12 ; CN2.5A 60.85,7 ; CN2.5A 59.4,5.8 ; CN2.5A 59.4,8.2 ; CN2.5A 58.05,7
  BOTTOM w0.6: CN2.5 59.4,13.2 ; CN2.5 58.05,12 ; CN2.5 59.4,10.8 ; CN2.5 60.65,12 ; CN2.7A 53.85,7 ; CN2.7A 51.05,7 ; CN2.7A 52.4,8.4 ; CN2.7A 52.4,5.6 ; CN2.5A 58.05,7 ; CN2.5A 60.85,7 ; CN2.5A 59.4,8.2 ; CN2.5A 59.4,5.8 ; CN2.7 51.05,12 ; CN2.7 52.4,10.8 ; CN2.7 52.4,13.4 ; CN2.7 53.85,12
  vias: v1(50.4,16) v1(50.4,15) v1(51.4,16) v1(51.4,15) v1(52.4,16) v1(52.4,15) v1(53.4,16) v1(53.4,15)
LOADC: length 42.4
  TOP w0.6: CN2.11 39.85,12 ; CN2.11 37.05,12 ; CN2.11 38.4,10.8 ; CN2.11 38.4,13.4 ; CN2.9A 44.05,7 ; CN2.9A 46.85,7 ; CN2.9A 45.4,5.8 ; CN2.9A 45.4,8.2 ; CN2.11A 37.05,7 ; CN2.11A 38.4,8.4 ; CN2.11A 39.85,7 ; CN2.11A 38.4,5.6 ; CN2.9 45.4,13.2 ; CN2.9 44.05,12 ; CN2.9 46.65,12 ; CN2.9 45.4,10.8
  BOTTOM w0.6: CN2.9A 45.4,8.2 ; CN2.9A 45.4,5.8 ; CN2.9A 44.05,7 ; CN2.9A 46.85,7 ; CN2.11A 38.4,8.4 ; CN2.11A 38.4,5.6 ; CN2.11A 39.85,7 ; CN2.11A 37.05,7 ; CN2.11 38.4,13.4 ; CN2.11 37.05,12 ; CN2.11 38.4,10.8 ; CN2.11 39.85,12 ; CN2.9 45.4,13.2 ; CN2.9 45.4,10.8 ; CN2.9 44.05,12 ; CN2.9 46.65,12
  vias: v1(37.25,15) v1(38.25,15) v1(39.25,15) v1(40.25,15) v1(43.4,15) v1(44.4,15) v1(45.4,15) v1(46.4,15)
LOADD: length 42.4
  TOP w0.6: CN2.13 32.65,12 ; CN2.13 30.05,12 ; CN2.13 31.4,13.2 ; CN2.13 31.4,10.8 ; CN2.13A 30.05,7 ; CN2.13A 32.85,7 ; CN2.13A 31.4,5.8 ; CN2.13A 31.4,8.2 ; CN2.15A 23.05,7 ; CN2.15A 24.4,5.6 ; CN2.15A 25.85,7 ; CN2.15A 24.4,8.4 ; CN2.15 24.4,10.8 ; CN2.15 23.05,12 ; CN2.15 25.85,12 ; CN2.15 24.4,13.4
  BOTTOM w0.6: CN2.13A 31.4,5.8 ; CN2.13A 30.05,7 ; CN2.13A 31.4,8.2 ; CN2.13A 32.85,7 ; CN2.15A 23.05,7 ; CN2.15A 24.4,5.6 ; CN2.15A 24.4,8.4 ; CN2.15A 25.85,7 ; CN2.13 31.4,13.2 ; CN2.13 31.4,10.8 ; CN2.13 32.65,12 ; CN2.13 30.05,12 ; CN2.15 24.4,13.4 ; CN2.15 24.4,10.8 ; CN2.15 25.85,12 ; CN2.15 23.05,12
  vias: v1(23.25,15) v1(24.25,15) v1(25.25,15) v1(26.25,15) v1(30.25,15) v1(31.25,15) v1(32.25,15) v1(33.25,15)
SIG15: length 1.5
  TOP w0.3: R5.1 20.2,86
SIG46: length 5.5
  TOP w0.15: 22,73.03 22.43,73.03 22.6,73.2 22.6,75.6 22,76.2 21.4,76.2 21,76.6 IC2.B1
SIG166: length 9.9
  TOP w0.15: IC2.A1 19.4,75.8 19.4,73.2 19.6,73 v1(19.9,72.9) 20.69,72.9 ; 21.31,70.5 v1(22.1,70.5)
  TOP w0.25: Q1.G 20.69,72.9 ; Q2.G 21.31,70.5
  BOTTOM w0.15: v1(19.9,72.9) v1(22.1,70.5)
SIG189: length 9.9
  TOP w0.15: 15.31,70.5 v1(16.1,70.5) ; IC3.A1 13.4,75.8 13.4,73.2 13.6,73 v1(13.9,72.9) 14.69,72.9
  TOP w0.25: Q3.G 14.69,72.9 ; Q4.G 15.31,70.5
  BOTTOM w0.15: v1(13.9,72.9) v1(16.1,70.5)
SIG190: length 5.5
  TOP w0.15: 16,73.03 16.43,73.03 16.6,73.2 16.6,75.6 16,76.2 15.4,76.2 15,76.6 IC3.B1
SIG193: length 1.2
  TOP w0.3: C19.2 11.8,85.75
SIG225: length 2.1
  TOP w0.3: 77.42,25.91 78.6,25.91
  TOP w0.6: IC5.6 77.42,25.91 ; 78.6,25.91 78.8,25.91
SIG229: length 5.3
  TOP w0.15: 73.35,30.04 73.35,29.05 73.6,28.8 73.6,27.8 72.97,27.18 71.87,27.18
  TOP w0.4: IC10.4 73.35,30.04
  TOP w0.6: 71.87,27.18 IC5.10
SIG230: length 4.3
  TOP w0.3: 70.58,20.82 69.41,20.82 ; 69.2,20.62 69.2,19.81 ; R7.2 69.2,19.45
  TOP w0.4: 69.2,19.81 D2.A
  TOP w0.55: 69.41,20.82 69.2,20.82
  TOP w0.6: IC5.15 70.58,20.82
  TOP w0.7: C8.2 69.2,20.62
SIG250: length 4.3
  TOP w0.3: 77.42,27.18 78.59,27.18 ; R6.2 78.8,28.55 ; 78.8,28.19 78.8,27.42
  TOP w0.4: D1.A 78.8,28.19
  TOP w0.55: 78.59,27.18 78.8,27.18
  TOP w0.6: IC5.7 77.42,27.18
  TOP w0.7: 78.8,27.42 C7.2
SIG275: length 18.9
  TOP w0.15: 76.75,33.6 77.45,33.6 ; SW1.4 75.6,48.1 75.6,40.6 SW1.2 77.55,37.4 77.55,34.9 ; R4.1 C5.1
  TOP w0.3: R14.2 76.75,33.6 ; R4.1 77.55,34.9
  TOP w0.7: 77.45,33.6 C5.1
SIG309: length 9
  TOP w0.15: SW2.L2 55.6,40.58 55.6,36.1 55,35.5 55,34.95
  TOP w0.3: 55,34.95 R2.1
SIG313: length 19
  TOP w0.15: 58.45,34.7 58.45,33.96 ; 58.45,34.9 58.45,37.4 SW2.2 60.8,41 60.8,47.7 SW2.4 ; 59.25,33.8 58.55,33.8
  TOP w0.3: 58.45,34.7 R3.1 58.45,34.9 ; R20.1 59.25,33.8
  TOP w0.7: 58.45,33.96 58.45,33.81 ; 58.55,33.8 C6.1
SIG315: length 18.7
  TOP w0.15: SW3.4 29.6,48.1 29.6,40.6 SW3.2 31.55,37.4 31.55,34.9 ; R9.1 C10.1 30.75,33.8
  TOP w0.3: 30.75,33.8 R16.2 ; R9.1 31.55,34.9
SIG318: length 4.3
  TOP w0.3: 23.8,28.19 23.8,27.42 ; 22.42,27.18 23.59,27.18 ; R11.2 23.8,28.55
  TOP w0.4: D3.A 23.8,28.19
  TOP w0.55: 23.59,27.18 23.8,27.18
  TOP w0.6: IC8.7 22.42,27.18
  TOP w0.7: 23.8,27.42 C16.1
SIG321: length 2.1
  TOP w0.3: 22.42,25.91 23.6,25.91
  TOP w0.6: 23.6,25.91 23.8,25.91 ; IC8.6 22.42,25.91
SIG324: length 5.3
  TOP w0.15: 18.35,30.04 18.35,29.05 18.6,28.8 18.6,27.8 17.98,27.18 16.87,27.18
  TOP w0.4: IC11.4 18.35,30.04
  TOP w0.6: 16.87,27.18 IC8.10
SIG326: length 9
  TOP w0.15: 9,34.95 9,35.5 9.6,36.1 9.6,40.58 SW4.L2
  TOP w0.3: 9,34.95 R13.1
SIG328: length 9
  TOP w0.15: SW3.L2 28.6,40.58 28.6,36.1 28,35.5 28,34.95
  TOP w0.3: 28,34.95 R8.1
SIG332: length 4.3
  TOP w0.3: R12.2 14.2,19.45 ; 15.58,20.82 14.41,20.82 ; 14.2,20.62 14.2,19.81
  TOP w0.4: 14.2,19.81 D4.A
  TOP w0.55: 14.41,20.82 14.2,20.82
  TOP w0.6: IC8.15 15.58,20.82
  TOP w0.7: C15.2 14.2,20.62
SIG333: length 19
  TOP w0.15: SW4.4 14.8,47.7 14.8,41 SW4.2 12.45,37.4 12.45,34.9 ; 12.45,34.7 12.45,33.96 ; 13.25,33.8 12.55,33.8
  TOP w0.3: 12.45,34.9 R10.1 12.45,34.7 ; R17.1 13.25,33.8
  TOP w0.7: 12.45,33.96 12.45,33.81 ; 12.55,33.8 C11.1
SIG335: length 1.8
  TOP w0.15: 14.55,24.6 15.61,24.6
  TOP w0.3: R18.2 14.55,24.6
  TOP w0.55: 15.61,24.6 16.27,24.6
SIG338: length 3.2
  TOP w0.15: 42.04,19.1 44.1,19.1 IC7.A1
  TOP w0.55: 42.04,19.1 Q11.4
SIG339: length 3.2
  TOP w0.15: 52.04,19.1 54.1,19.1 IC6.A1
  TOP w0.55: 52.04,19.1 Q9.4
SIG340: length 3
  TOP w0.15: 62.13,19.5 64.5,19.5 IC4.A1
  TOP w0.3: 61.91,19.5 62.13,19.5
SIG341: length 3.2
  TOP w0.15: IC9.A1 34.1,19.1 32.04,19.1
  TOP w0.55: 32.04,19.1 Q13.4
SIG345: length 14.1
  TOP w0.15: 59.95,33.8 70.8,33.8 72.22,32.38 73.25,32.38
  TOP w0.3: R20.2 59.95,33.8
  TOP w0.4: 73.25,32.38 IC10.3
SIG347: length 29.1
  TOP w0.15: v1(12,21.2) 11,22.2 11,22.65 ; v1(35,18.6) 35.8,18.6 36.2,19 36.2,20 36,20.2 IC9.C2
  TOP w0.3: R19.2 11,22.65
  BOTTOM w0.15: v1(35,18.6) 20.2,18.6 18,20.8 12.4,20.8 v1(12,21.2)
SIG348: length 10.8
  TOP w0.15: 13.85,24.6 13.4,24.6 12.6,25.4 12.6,26.2 v1(11.4,27.4)
  TOP w0.3: 13.85,24.6 R18.1
  BOTTOM w0.15: v1(11.4,27.4) 9,27.4 SW5.1
SIG3334: length 1.8
  TOP w0.3: Q5.C LED1.C
SIG3335: length 25.3
  TOP w0.15: 78.92,24.65 80.4,24.65 83,27.25 83,40.2 79.2,44 SW1.LC
  TOP w0.5: 78.92,24.65 Q6.C
SIG3337: length 33.5
  TOP w0.15: 69.08,23.2 67.2,23.2 66.4,24 66.4,31 64.6,32.8 56.4,32.8 55.8,33.4 55.8,34.8 56.6,35.6 56.6,42.06 SW2.LC
  TOP w0.5: 69.08,23.2 69.2,23.2
SIG3338: length 31.5
  TOP w0.15: SW3.LC 33,44 36.8,40.2 36.8,35.6 31.8,30.6 26.8,30.6 25.8,29.6 25.8,25.2 25.25,24.65 23.93,24.65
  TOP w0.5: 23.93,24.65 Q10.C
SIG3340: length 20.8
  TOP w0.15: SW4.LC 10.6,42.06 10.6,35.6 9.8,34.8 9.8,26.2 10.55,25.45 11.28,25.45
  TOP w0.5: 11.28,25.45 Q12.C
SIG3348: length 9
  TOP w0.15: SW1.L2 74.6,40.58 74.6,36.1 74,35.5 74,34.95
  TOP w0.3: 74,34.95 R1.1
SIG3352: length 11.7
  TOP w0.15: 76.22,20.82 74.97,20.82 74.4,21.4 74.4,28.8 74.65,29.05 74.65,30.04
  TOP w0.4: IC10.6 74.65,30.04
  TOP w0.6: 76.22,20.82 IC5.2
SIG3353: length 2
  TOP w0.15: 74.72,32.6 75.15,32.6 R14.1
  TOP w0.3: 74.6,32.6 74.72,32.6
SIG3354: length 11.7
  TOP w0.15: 21.23,20.82 19.98,20.82 19.4,21.4 19.4,28.8 19.65,29.05 19.65,30.04
  TOP w0.4: IC11.6 19.65,30.04
  TOP w0.6: 21.23,20.82 IC8.2
SIG3355: length 11.1
  TOP w0.15: 19.75,32.38 20.18,32.38 20.8,33 28.4,33 29.2,33.8 30.05,33.8
  TOP w0.3: R16.1 30.05,33.8
  TOP w0.4: 19.75,32.38 IC11.1
SIG3356: length 5.1
  TOP w0.15: 13.95,33.8 15,33.8 16.43,32.38 18.24,32.38
  TOP w0.3: 13.95,33.8 R17.2
  TOP w0.4: IC11.3 18.24,32.38
SIG3359: length 31.6
  TOP w0.15: SW6.3 65.6,89.3 64.45,89.3 60.85,85.7 60.85,75.75 56.48,71.38 CN4.3
SIG3360: length 37.4
  TOP w0.15: CN4.2 53.06,70.8 56.85,70.8 61.45,75.4 61.45,85.5 64.75,88.8 69.8,88.8 SW6.2
SIG3361: length 43.2
  TOP w0.15: CN4.1 55,70.2 57.25,70.2 62,74.95 62,85.15 65.05,88.2 73.9,88.2 SW6.1
SW_CONTA: length 27.2
  TOP w0.15: IC4.C2 66.2,20.2 66.6,19.8 v1(66.6,19) ; 78.4,23.1 78.4,22.8 78.6,22.6 80.4,22.6 80.8,22.2 80.8,19.4 77.6,16.2 v1(76.4,16.2) ; 77.36,23.36 78.28,23.36
  TOP w0.37: 78.28,23.36 78.39,23.36
  TOP w0.4: 78.4,23.1 Q6.B
  TOP w0.6: IC5.4 77.36,23.36
  BOTTOM w0.15: v1(76.4,16.2) 75.8,16.8 67.2,16.8 66.6,17.4 v1(66.6,19)
SW_CONTB: length 24
  TOP w0.15: v1(67.6,26.2) 68.2,25.6 69.4,25.6 69.6,25.4 69.6,24.9 ; IC6.C2 56,20.2 56.2,20 56.2,19 v1(56,18.6) ; 70.64,24.64 69.71,24.64
  TOP w0.4: 69.6,24.9 Q8.B ; 69.71,24.64 69.6,24.64
  TOP w0.6: IC5.12 70.64,24.64
  BOTTOM w0.15: v1(56,18.6) 57,19.6 65,19.6 66.6,21.2 66.6,25.2 v1(67.6,26.2)
SW_CONTC: length 29.6
  TOP w0.15: IC7.C2 46,20.2 46.2,20 46.2,19 45.8,18.6 v1(45,18.6) ; v1(25.4,20.4) 25.4,22 24.8,22.6 23.6,22.6 23.4,22.8 23.4,23.1 ; 22.36,23.36 23.29,23.36
  TOP w0.4: Q10.B 23.4,23.1 ; 23.29,23.36 23.4,23.36
  TOP w0.6: IC8.4 22.36,23.36
  BOTTOM w0.15: v1(45,18.6) 38,18.6 36.2,20.4 v1(25.4,20.4)
SW_CONTD: length 6.9
  TOP w0.15: 11,23.35 11,23.84 ; SW5.2 8.45,23.25 10.9,23.25
  TOP w0.3: 10.9,23.25 R19.1 11,23.35
  TOP w0.4: 11,23.84 Q12.B
VOUT: length 29.7
  TOP w0.2: 44.8,20.7 IC7.A2 44.25,20.2 ; 54.8,20.7 IC6.A2 54.25,20.2 ; 64.8,20.7 IC4.A2 64.25,20.2 ; 34.8,20.7 IC9.A2 34.25,20.2
  TOP w0.45: C9.1 44.77,21.3 ; C9.1 44.25,22 ; C9.1 44.77,22.65 ; C3.1 64.25,22 ; C3.1 64.78,21.3 ; C3.1 64.78,22.65 ; C4.1 54.77,22.65 ; C4.1 54.77,21.3 ; C4.1 54.25,22 ; C12.1 34.25,22 ; C12.1 34.77,22.65 ; C12.1 34.77,21.3
  TOP w0.6: CN5.6 32.4,66.3 ; CN5.6 33.9,64.8 ; CN5.6 35.6,66.3 ; 32.4,68.84 CN5.5 35.8,68.84
  BOTTOM w0.6: TP3.1 25.8,60 ; TP3.1 27,58.8 ; TP3.1 28.2,60 ; TP3.1 27,61.2
  BOTTOM w1: CN5.6 35.6,66.3 ; CN5.6 32.2,66.3 ; CN5.6 33.9,64.6
  vias: v1(27,28.4) v1(27,27.4) v1(27,26.4) v1(27,25.4) v1(27,24.4) v1(27,23.4) v1(27,22.4) v1(28,28.4) v1(28,27.4) v1(28,26.4) v1(29,28.4) v1(29,27.4) v1(29,26.4) v1(30,28.4) v1(30,27.4) v1(30,26.4) v1(31,28.4) v1(31,27.4) v1(31,26.4) v1(32,28.4) v1(32,27.4) v1(32,26.4) v1(33,28.4) v1(33,27.4) v1(33,26.4) v1(33,25.4) v1(33,24.4) v1(33,23.4) v1(33,22.4) v1(34.4,63.4) v1(34.4,62) v1(35.4,63.4) v1(35.4,62) v1(36.4,63.4) v1(36.4,62) v1(37,28.4) v1(37,27.4) v1(37,26.4) v1(37,25.4) v1(37,24.4) v1(37,23.4) v1(37,22.4) v1(37.4,63.4) v1(37.4,62) v1(38,28.4) v1(38,27.4) v1(38,26.4) v1(39,28.4) v1(39,27.4) v1(39,26.4) v1(40,28.4) v1(40,27.4) v1(40,26.4) v1(41,28.4) v1(41,27.4) v1(41,26.4) v1(42,28.4) v1(42,27.4) v1(42,26.4) v1(43,28.4) v1(43,27.4) v1(43,26.4) v1(43,25.4) v1(43,24.4) v1(43,23.4) v1(43,22.4) v1(47,28.4) v1(47,27.4) v1(47,26.4) v1(47,25.4) v1(47,24.4) v1(47,23.4) v1(47,22.4) v1(48,28.4) v1(48,27.4) v1(48,26.4) v1(49,28.4) v1(49,27.4) v1(49,26.4) v1(50,28.4) v1(50,27.4) v1(50,26.4) v1(51,28.4) v1(51,27.4) v1(51,26.4) v1(52,28.4) v1(52,27.4) v1(52,26.4) v1(53,28.4) v1(53,27.4) v1(53,26.4) v1(53,25.4) v1(53,24.4) v1(53,23.4) v1(53,22.4) v1(57,28.4) v1(57,27.4) v1(57,26.4) v1(57,25.4) v1(57,24.4) v1(57,23.4) v1(57,22.4) v1(58,28.4) v1(58,27.4) v1(58,26.4) v1(59,28.4) v1(59,27.4) v1(59,26.4) v1(60,28.4) v1(60,27.4) v1(60,26.4) v1(61,28.4) v1(61,27.4) v1(61,26.4) v1(62,28.4) v1(62,27.4) v1(62,26.4) v1(63,28.4) v1(63,27.4) v1(63,26.4) v1(63,25.4) v1(63,24.4) v1(63,23.4) v1(63,22.4)
VP_4R8: length 35.6
  TOP w0.25: 20.87,31.15 20.45,31.15 20.4,31.2 19.2,31.2 19,31 19,30.7 ; 75.87,31.15 75.45,31.15 75.4,31.2 74.2,31.2 74,31 74,30.7
  TOP w0.3: R12.1 v1(13.2,18.2) 14.2,18.2 ; v1(21,30.4) C21.2 20.87,31.15 ; 70.58,25.91 69.89,25.91 69.6,26.2 v1(69,26.2) ; 23.8,29.8 v1(24.8,29.8) R11.1 ; 13.9,77.4 IC3.A2 14.55,77.45 14.55,77.85 14.4,78 ; v1(76,30.4) C20.2 75.87,31.15 ; 22.42,22.09 23.8,22.09 23.86,22.08 v1(24.2,22) ; 15.58,25.91 v1(13.8,25.91) ; 16.75,19.55 C14.2 v1(16,18) ; v1(12,22.8) 11.8,23 11.8,23.74 ; v1(68,24.8) 68.8,24.8 ; 69.2,18.2 v1(68.2,18.2) R7.1 ; R6.1 v1(79.8,29.8) 78.8,29.8 ; 77.42,22.09 78.8,22.09 78.86,22.08 v1(79.2,22) ; 71.75,19.55 C13.2 v1(71,18) ; v1(25,23.35) 24.36,23.35 ; v1(80,23.35) 79.36,23.35
  TOP w0.4: 24.36,23.35 Q10.E ; 74,30.7 IC10.5 ; 14.38,79.3 C2.1 14.38,79.92 14.2,80.1 ; 14.38,79.3 13.8,79.3 ; 14.38,79.3 14.38,78.7 ; 19,30.7 IC11.5 ; 79.36,23.35 Q6.E ; Q12.E 11.8,23.74
  TOP w0.6: IC8.11 15.58,25.91 ; 70.58,25.91 IC5.11 ; IC8.3 22.42,22.09 ; IC5.3 77.42,22.09
  vias: v1(14.6,75.4) v1(14.6,74.6) v1(14.8,84) v1(14.8,83) v1(14.8,82) v1(15.4,75.4) v1(15.4,74.6) v1(15.8,84) v1(15.8,83) v1(15.8,82) v1(33.6,57.8) v1(33.6,56.8) v1(33.6,55.8) v1(34.6,57.8) v1(34.6,56.8) v1(34.6,55.8) v1(55.8,55.6) v1(55.8,54.6) v1(55.8,53.6) v1(56.8,55.6) v1(56.8,54.6) v1(56.8,53.6)

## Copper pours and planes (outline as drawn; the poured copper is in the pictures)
GND on TOP: outline of 118 points within 31.55,13.05 43.85,29.85
GND on TOP: outline of 122 points within 51.77,13.05 64,29.85
GND on TOP: 55.9,13.05 54.88,13.05 54.82,13.07 54.8,13.12 54.8,13.7 54.81,13.76 54.87,13.87 54.93,13.92 55.05,13.95 56.75,13.95 56.81,13.94 56.92,13.88 56.97,13.82 57,13.7 57,13.3 56.97,13.17 56.88,13.08 56.75,13.05
GND on TOP: 8,4 6.83,6.83 4,8 0.57,8 0.52,8.02 0.5,8.07 0.5,99.92 0.52,99.98 0.57,100 4,100 6.83,101.17 8,104 8,107.42 8.02,107.48 8.07,107.5 76.92,107.5 76.98,107.48 77,107.42 77,104 78.17,101.17 81,100 84.42,100 84.48,99.98 84.5,99.92 84.5,8.07 84.48,8.02 84.42,8 81,8 78.17,6.83 77,4 77,0.57 76.98,0.52 76.92,0.5 8.07,0.5 8.02,0.52 8,0.57 ; 67 cut-outs
GND on TOP: outline of 151 points within 14.75,68.15 22.18,85.4
GND on TOP: outline of 119 points within 41.57,13.05 53.85,29.85
GND on TOP, BOTTOM: 69.05,8.05 68.92,8.08 68.83,8.18 68.8,8.3 68.8,10.7 68.83,10.82 68.92,10.92 69.05,10.95 70.75,10.95 70.88,10.92 70.97,10.82 71,10.7 71,8.3 70.97,8.18 70.88,8.08 70.75,8.05
GND on TOP, BOTTOM: 34.05,8.05 33.92,8.08 33.83,8.18 33.8,8.3 33.8,10.7 33.83,10.82 33.92,10.92 34.05,10.95 35.75,10.95 35.88,10.92 35.97,10.82 36,10.7 36,8.3 35.97,8.18 35.88,8.08 35.75,8.05
GND on TOP, BOTTOM: 62.05,8.05 61.92,8.08 61.83,8.18 61.8,8.3 61.8,10.7 61.83,10.82 61.92,10.92 62.05,10.95 63.75,10.95 63.88,10.92 63.97,10.82 64,10.7 64,8.3 63.97,8.18 63.88,8.08 63.75,8.05
GND on TOP, BOTTOM: 27.05,8.05 26.93,8.08 26.83,8.18 26.8,8.3 26.8,10.7 26.83,10.82 26.93,10.92 27.05,10.95 28.75,10.95 28.88,10.92 28.97,10.82 29,10.7 29,8.3 28.97,8.18 28.88,8.08 28.75,8.05
GND on TOP, BOTTOM: 41.05,8.05 40.92,8.08 40.83,8.18 40.8,8.3 40.8,10.7 40.83,10.82 40.92,10.92 41.05,10.95 42.75,10.95 42.88,10.92 42.97,10.82 43,10.7 43,8.3 42.97,8.18 42.88,8.08 42.75,8.05
GND on TOP, BOTTOM: 48.05,8.05 47.92,8.08 47.83,8.18 47.8,8.3 47.8,10.7 47.83,10.82 47.92,10.92 48.05,10.95 49.75,10.95 49.88,10.92 49.97,10.82 50,10.7 50,8.3 49.97,8.18 49.88,8.08 49.75,8.05
GND on TOP, BOTTOM: 55.05,8.05 54.92,8.08 54.83,8.18 54.8,8.3 54.8,10.7 54.83,10.82 54.92,10.92 55.05,10.95 56.75,10.95 56.88,10.92 56.97,10.82 57,10.7 57,8.3 56.97,8.18 56.88,8.08 56.75,8.05
GND on BOTTOM: 8,4 6.83,6.83 4,8 0.57,8 0.52,8.02 0.5,8.07 0.5,99.92 0.52,99.98 0.57,100 4,100 6.83,101.17 8,104 8,107.42 8.02,107.48 8.07,107.5 76.92,107.5 76.98,107.48 77,107.42 77,104 78.17,101.17 81,100 84.42,100 84.48,99.98 84.5,99.92 84.5,8.07 84.48,8.02 84.42,8 81,8 78.17,6.83 77,4 77,0.57 76.98,0.52 76.92,0.5 8.07,0.5 8.02,0.52 8,0.57 ; 76 cut-outs
GND on BOTTOM: 29.25,82 29.75,82
GND on BOTTOM: 55.05,13.05 54.92,13.08 54.83,13.18 54.8,13.3 54.8,13.9 54.83,13.97 54.9,14 56.9,14 56.97,13.97 57,13.9 57,13.3 56.97,13.18 56.88,13.08 56.75,13.05
GND on CONDUCTIVE2: 8,4 6.83,6.83 4,8 0.57,8 0.52,8.02 0.5,8.07 0.5,99.92 0.52,99.98 0.57,100 4,100 6.83,101.17 8,104 8,107.42 8.02,107.48 8.07,107.5 76.92,107.5 76.98,107.48 77,107.42 77,104 78.17,101.17 81,100 84.42,100 84.48,99.98 84.5,99.92 84.5,8.07 84.48,8.02 84.42,8 81,8 78.17,6.83 77,4 77,0.57 76.98,0.52 76.92,0.5 8.07,0.5 8.02,0.52 8,0.57 ; 371 cut-outs
GND on CONDUCTIVE3: 8,4 6.83,6.83 4,8 0.57,8 0.52,8.02 0.5,8.07 0.5,97.92 0.52,97.98 0.57,98 5,98 8.54,99.46 10,103 10,107.42 10.02,107.48 10.07,107.5 74.92,107.5 74.98,107.48 75,107.42 75,103 76.46,99.46 80,98 84.42,98 84.48,97.98 84.5,97.92 84.5,8.07 84.48,8.02 84.42,8 81,8 78.17,6.83 77,4 77,0.57 76.98,0.52 76.92,0.5 8.07,0.5 8.02,0.52 8,0.57 ; 371 cut-outs
VDD on TOP: 13.43,91.42 13.53,91.52 13.65,91.55 16.55,91.55 16.68,91.52 16.77,91.42 16.8,91.3 16.8,88.15 16.77,88.03 16.68,87.93 16.55,87.9 13.47,87.9 13.42,87.92 13.4,87.97 13.4,89.65 13.42,89.7 13.47,89.72 13.78,89.72 13.97,89.81 14.05,90 14.05,90.4 13.97,90.59 13.78,90.67 13.47,90.67 13.42,90.7 13.4,90.75 13.4,91.3 ; 1 cut-out
VDD on TOP: 49.35,88.45 49.28,88.27 49.1,88.2 46.4,88.2 46.27,88.23 46.18,88.33 46.15,88.45 46.15,102.35 46.18,102.47 46.27,102.57 46.4,102.6 49.1,102.6 49.23,102.57 49.32,102.47 49.35,102.35 49.35,91.15 49.33,91.1 49.27,91.08 48.98,91.08 48.78,90.99 48.7,90.8 48.7,90.4 48.78,90.21 48.98,90.12 49.27,90.12 49.33,90.1 49.35,90.05 ; 2 cut-outs
VDD on BOTTOM: 46.32,89.83 46.21,89.89 46.15,89.9 14.25,89.9 14.12,89.93 14.03,90.03 14,90.15 14,91.65 14.03,91.78 14.12,91.87 14.25,91.9 47.15,91.9 47.21,91.89 47.32,91.83 49.28,89.87 49.33,89.79 49.35,89.7 49.35,88.45 49.28,88.27 49.1,88.2 48.05,88.2 47.96,88.22 47.88,88.27
VINA on TOP: 33.55,87.85 33.48,87.67 33.3,87.6 28.8,87.6 28.62,87.67 28.55,87.85 28.55,92.7 28.57,92.79 28.62,92.87 31.68,95.93 31.73,96.01 31.75,96.1 31.75,102.55 31.78,102.67 31.88,102.77 32,102.8 35.5,102.8 35.62,102.77 35.72,102.67 35.75,102.55 35.75,94.3 35.74,94.24 35.68,94.13 33.62,92.07 33.56,91.96 33.55,91.9 33.55,91.15 33.53,91.1 33.48,91.08 33.17,91.08 32.98,90.99 32.9,90.8 32.9,90.4 32.98,90.21 33.17,90.12 33.48,90.12 33.53,90.1 33.55,90.05 ; 2 cut-outs
VINA on TOP: 19.8,75.34 19.81,75.4 19.84,75.44 20.16,75.76 20.2,75.79 20.26,75.8 21.74,75.8 21.84,75.76 22.16,75.44 22.2,75.34 22.2,73.45 22.16,73.34 22.05,73.3 19.95,73.3 19.84,73.34 19.8,73.45 ; 2 cut-outs
VINA on TOP: 19.55,77.25 19.44,77.29 19.4,77.4 19.4,81.05 19.44,81.16 19.55,81.2 20.45,81.2 20.56,81.16 20.6,81.05 20.6,79.85 20.58,79.8 20.52,79.78 20.23,79.78 20.03,79.69 19.95,79.5 19.95,79.1 20.03,78.91 20.23,78.83 20.52,78.83 20.58,78.8 20.6,78.75 20.6,77.87 20.58,77.81 20.52,77.79 20.46,77.79 20.3,77.73 20.24,77.57 20.24,77.33 20.22,77.27 20.16,77.25
VINA on BOTTOM: 18.8,81.5 18.82,81.59 18.87,81.67 26.33,89.13 26.41,89.18 26.5,89.2 33.35,89.2 33.53,89.13 33.6,88.95 33.6,86.1 33.62,86.01 33.67,85.93 36.73,82.87 36.78,82.79 36.8,82.7 36.8,76 36.73,75.82 36.55,75.75 25.25,75.75 25.16,75.73 25.08,75.68 23.65,74.25 23.57,74.19 23.47,74.17 20.25,74.17 20.07,74.25 20,74.42 20,75.55 20.07,75.73 20.25,75.8 22.5,75.8 22.59,75.82 22.67,75.87 23.53,76.73 23.58,76.81 23.6,76.9 23.6,80.3 23.57,80.42 23.53,80.47 22.47,81.53 22.36,81.59 22.3,81.6 20.85,81.6 20.73,81.57 20.63,81.47 20.6,81.35 20.6,79.9 20.59,79.84 20.53,79.73 20.47,79.67 20.39,79.62 20.3,79.6 19.3,79.6 19.21,79.62 19.13,79.67 18.87,79.93 18.82,80.01 18.8,80.1 ; 3 cut-outs
VINA on BOTTOM: 31.75,102.55 31.82,102.73 32,102.8 35.5,102.8 35.62,102.77 35.72,102.67 35.75,102.55 35.75,92.95 35.72,92.83 35.62,92.73 35.5,92.7 31,92.7 30.88,92.73 30.78,92.83 30.75,92.95 30.75,94.9 30.76,94.96 30.82,95.07 31.68,95.93 31.73,96.01 31.75,96.1 ; 2 cut-outs
VINB on TOP: 42.35,87.85 42.28,87.67 42.1,87.6 37.6,87.6 37.42,87.67 37.35,87.85 37.35,92.7 37.37,92.79 37.42,92.87 38.68,94.13 38.73,94.21 38.75,94.3 38.75,102.55 38.78,102.67 38.88,102.77 39,102.8 42.6,102.8 42.73,102.77 42.82,102.67 42.85,102.55 42.85,92.6 42.84,92.54 42.78,92.43 42.42,92.07 42.36,91.96 42.35,91.9 42.35,91.15 42.33,91.1 42.27,91.08 41.98,91.08 41.78,90.99 41.7,90.8 41.7,90.4 41.78,90.21 41.98,90.12 42.27,90.12 42.33,90.1 42.35,90.05 ; 2 cut-outs
VINB on BOTTOM: 46.33,83.07 46.41,83.02 46.5,83 57.3,83 57.39,82.98 57.47,82.93 59.33,81.07 59.38,80.99 59.4,80.9 59.4,79.5 59.38,79.41 59.33,79.33 55.82,75.82 55.74,75.77 55.65,75.75 46.35,75.75 46.26,75.77 46.18,75.82 37.37,84.63 37.33,84.68 37.3,84.8 37.3,89.13 37.32,89.18 37.37,89.2 42.33,89.2 42.38,89.18 42.4,89.13 42.4,87 ; 2 cut-outs
VINB on BOTTOM: 38.75,102.73 38.77,102.78 38.82,102.8 42.55,102.8 42.67,102.77 42.77,102.67 42.8,102.55 42.8,92.95 42.77,92.83 42.67,92.73 42.55,92.7 39,92.7 38.88,92.73 38.78,92.83 38.75,92.95 ; 2 cut-outs
LOADA on TOP: 61.4,18.6 61.42,18.51 61.56,18.37 61.65,18.35 65.95,18.35 66.04,18.33 66.12,18.28 67.33,17.07 72.62,17.07 72.69,17.07 72.8,17 75.58,14.22 75.62,14.17 75.65,14.05 75.65,6.35 75.64,6.29 75.58,6.18 74.67,5.27 74.59,5.22 74.5,5.2 72.3,5.2 72.21,5.22 72.13,5.27 71.22,6.18 71.17,6.26 71.15,6.35 71.15,13.95 71.08,14.13 70.9,14.2 68.9,14.2 68.72,14.13 68.65,13.95 68.65,6.35 68.63,6.26 68.58,6.18 67.67,5.27 67.59,5.22 67.5,5.2 65.3,5.2 65.21,5.22 65.13,5.27 64.22,6.18 64.17,6.26 64.15,6.35 64.15,13.85 64.12,13.97 64.03,14.07 63.9,14.1 60,14.1 59.94,14.11 59.83,14.17 57.07,16.93 57.02,17.01 57,17.1 57,19.35 57.07,19.53 57.25,19.6 61.15,19.6 61.33,19.53 61.4,19.35 ; 4 cut-outs
LOADA on BOTTOM: 68.65,6.35 68.63,6.26 68.58,6.18 67.67,5.27 67.59,5.22 67.5,5.2 65.3,5.2 65.21,5.22 65.13,5.27 64.22,6.18 64.17,6.26 64.15,6.35 64.15,15.15 64.18,15.28 64.28,15.37 64.4,15.4 68.4,15.4 68.53,15.37 68.62,15.28 68.65,15.15 ; 2 cut-outs
LOADA on BOTTOM: 75.65,6.35 75.63,6.26 75.58,6.18 74.67,5.27 74.59,5.22 74.5,5.2 72.3,5.2 72.21,5.22 72.13,5.27 71.22,6.18 71.17,6.26 71.15,6.35 71.15,15.15 71.18,15.28 71.28,15.37 71.4,15.4 75.4,15.4 75.53,15.37 75.62,15.28 75.65,15.15 ; 2 cut-outs
LOADB on TOP: 51.43,18.38 51.47,18.33 52.13,17.67 52.24,17.61 52.3,17.6 55.37,17.6 55.4,17.59 55.42,17.58 59.33,13.67 59.44,13.61 59.5,13.6 60.15,13.6 60.24,13.58 60.32,13.53 61.58,12.27 61.63,12.19 61.65,12.1 61.65,6.35 61.63,6.26 61.58,6.18 60.67,5.27 60.59,5.22 60.5,5.2 58.3,5.2 58.21,5.22 58.13,5.27 57.22,6.18 57.17,6.26 57.15,6.35 57.15,13.7 57.12,13.85 57.03,13.98 57.03,13.98 56.9,14.07 56.75,14.1 55.05,14.1 54.9,14.07 54.77,13.98 54.77,13.98 54.68,13.85 54.65,13.7 54.65,6.35 54.63,6.26 54.58,6.18 53.67,5.27 53.59,5.22 53.5,5.2 51.3,5.2 51.21,5.22 51.13,5.27 50.22,6.18 50.17,6.26 50.15,6.35 50.15,13.15 50.13,13.24 50.08,13.32 47.07,16.33 47.02,16.41 47,16.5 47,19.4 47.07,19.58 47.25,19.65 51.33,19.65 51.38,19.63 51.4,19.58 51.4,18.5 ; 4 cut-outs
LOADB on BOTTOM: 58.3,5.2 58.21,5.22 58.13,5.27 57.22,6.18 57.17,6.26 57.15,6.35 57.15,13.9 57.08,14.08 56.9,14.15 54.9,14.15 54.72,14.08 54.65,13.9 54.65,6.35 54.63,6.26 54.58,6.18 53.67,5.27 53.59,5.22 53.5,5.2 51.3,5.2 51.21,5.22 51.13,5.27 50.22,6.18 50.17,6.26 50.15,6.35 50.15,17.15 50.18,17.27 50.27,17.37 50.4,17.4 58.3,17.4 58.36,17.39 58.47,17.33 61.58,14.22 61.62,14.17 61.65,14.05 61.65,6.35 61.64,6.29 61.58,6.18 60.67,5.27 60.59,5.22 60.5,5.2 ; 4 cut-outs
LOADC on TOP: 41.4,18.3 41.42,18.21 41.47,18.13 42.52,17.07 44.82,17.07 44.92,17.06 45,17 47.58,14.42 47.63,14.34 47.65,14.25 47.65,6.35 47.63,6.26 47.58,6.18 46.67,5.27 46.59,5.22 46.5,5.2 44.3,5.2 44.21,5.22 44.13,5.27 43.22,6.18 43.17,6.26 43.15,6.35 43.15,13.95 43.08,14.13 42.9,14.2 40.9,14.2 40.72,14.13 40.65,13.95 40.65,6.35 40.63,6.26 40.58,6.18 39.67,5.27 39.59,5.22 39.5,5.2 37.3,5.2 37.21,5.22 37.13,5.27 36.22,6.18 36.18,6.23 36.15,6.35 36.15,17.45 36.16,17.51 36.22,17.62 36.93,18.33 36.99,18.44 37,18.5 37,19.4 37.03,19.52 37.12,19.62 37.25,19.65 41.15,19.65 41.33,19.58 41.4,19.4 ; 4 cut-outs
LOADC on BOTTOM: 47.65,6.35 47.63,6.26 47.58,6.18 46.67,5.27 46.59,5.22 46.5,5.2 44.3,5.2 44.21,5.22 44.13,5.27 43.22,6.18 43.17,6.26 43.15,6.35 43.15,15.15 43.18,15.28 43.27,15.37 43.4,15.4 47.4,15.4 47.52,15.37 47.62,15.28 47.65,15.15 ; 2 cut-outs
LOADC on BOTTOM: 40.65,6.35 40.63,6.26 40.58,6.18 39.67,5.27 39.59,5.22 39.5,5.2 37.3,5.2 37.21,5.22 37.13,5.27 36.22,6.18 36.17,6.26 36.15,6.35 36.15,15.15 36.18,15.28 36.27,15.37 36.4,15.4 40.4,15.4 40.52,15.37 40.62,15.28 40.65,15.15 ; 2 cut-outs
LOADD on TOP: 22.15,14.25 22.17,14.34 22.22,14.42 26.33,18.53 26.38,18.61 26.4,18.7 26.4,19.4 26.47,19.58 26.65,19.65 31.15,19.65 31.27,19.62 31.37,19.52 31.4,19.4 31.4,18.1 31.43,17.98 31.47,17.93 33.58,15.82 33.62,15.77 33.65,15.65 33.65,6.35 33.64,6.29 33.58,6.18 32.67,5.27 32.59,5.22 32.5,5.2 30.3,5.2 30.21,5.22 30.13,5.27 29.22,6.18 29.17,6.26 29.15,6.35 29.15,13.95 29.08,14.13 28.9,14.2 26.9,14.2 26.72,14.13 26.65,13.95 26.65,6.35 26.63,6.26 26.58,6.18 25.67,5.27 25.59,5.22 25.5,5.2 23.3,5.2 23.21,5.22 23.13,5.27 22.22,6.18 22.17,6.26 22.15,6.35 ; 4 cut-outs
LOADD on BOTTOM: 33.65,6.35 33.63,6.26 33.58,6.18 32.67,5.27 32.59,5.22 32.5,5.2 30.3,5.2 30.21,5.22 30.13,5.27 29.22,6.18 29.18,6.23 29.15,6.35 29.15,15.15 29.18,15.28 29.27,15.37 29.4,15.4 33.4,15.4 33.58,15.33 33.65,15.15 ; 2 cut-outs
LOADD on BOTTOM: 26.65,6.35 26.63,6.26 26.58,6.18 25.67,5.27 25.59,5.22 25.5,5.2 23.3,5.2 23.21,5.22 23.13,5.27 22.22,6.18 22.17,6.26 22.15,6.35 22.15,15.15 22.18,15.28 22.27,15.37 22.4,15.4 26.4,15.4 26.52,15.37 26.62,15.28 26.65,15.15 ; 2 cut-outs
SIG46 on TOP: 21.1,73.03 21.12,73.08 21.17,73.1 22.05,73.1 22.16,73.06 22.2,72.95 22.2,71.05 22.16,70.94 22.05,70.9 20.9,70.9 20.9,70.37 20.88,70.32 20.83,70.3 19.95,70.3 19.84,70.34 19.8,70.45 19.8,72.35 19.84,72.46 19.95,72.5 21.1,72.5 ; 2 cut-outs
SIG190 on TOP: 15.1,73.03 15.12,73.08 15.17,73.1 16.05,73.1 16.16,73.06 16.2,72.95 16.2,71.05 16.16,70.94 16.05,70.9 14.9,70.9 14.9,70.37 14.88,70.32 14.83,70.3 13.95,70.3 13.84,70.34 13.8,70.45 13.8,72.35 13.84,72.46 13.95,72.5 15.1,72.5 ; 2 cut-outs
SIG3359 on TOP (solid shape): 67.1,92.06 67.18,92.13 67.25,92.06 67.24,91.78 68.08,90.94 68.35,90.95 68.43,90.88 68.36,90.8 67.12,90.74 67.06,90.76 67.04,90.82
SIG3360 on TOP (solid shape): 71.8,92.06 71.88,92.13 71.95,92.06 71.94,91.78 72.78,90.94 73.05,90.95 73.13,90.88 73.06,90.8 71.82,90.74 71.76,90.76 71.74,90.82
SIG3361 on TOP (solid shape): 76.5,92.06 76.58,92.13 76.65,92.06 76.64,91.78 77.48,90.94 77.75,90.95 77.83,90.88 77.76,90.8 76.52,90.74 76.46,90.76 76.44,90.82
